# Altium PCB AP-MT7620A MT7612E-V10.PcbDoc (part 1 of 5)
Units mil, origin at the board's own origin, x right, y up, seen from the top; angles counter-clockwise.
Board outline 4645.67 x 3740.16 mil, 4 copper layers (Top, Inner Layer 2, Inner Layer 3, Bottom), stack 35.4 mil thick; 603 components, 409 nets, 1850 pads, 2004 vias.
Unrouted connection lines stored in the file: 90.
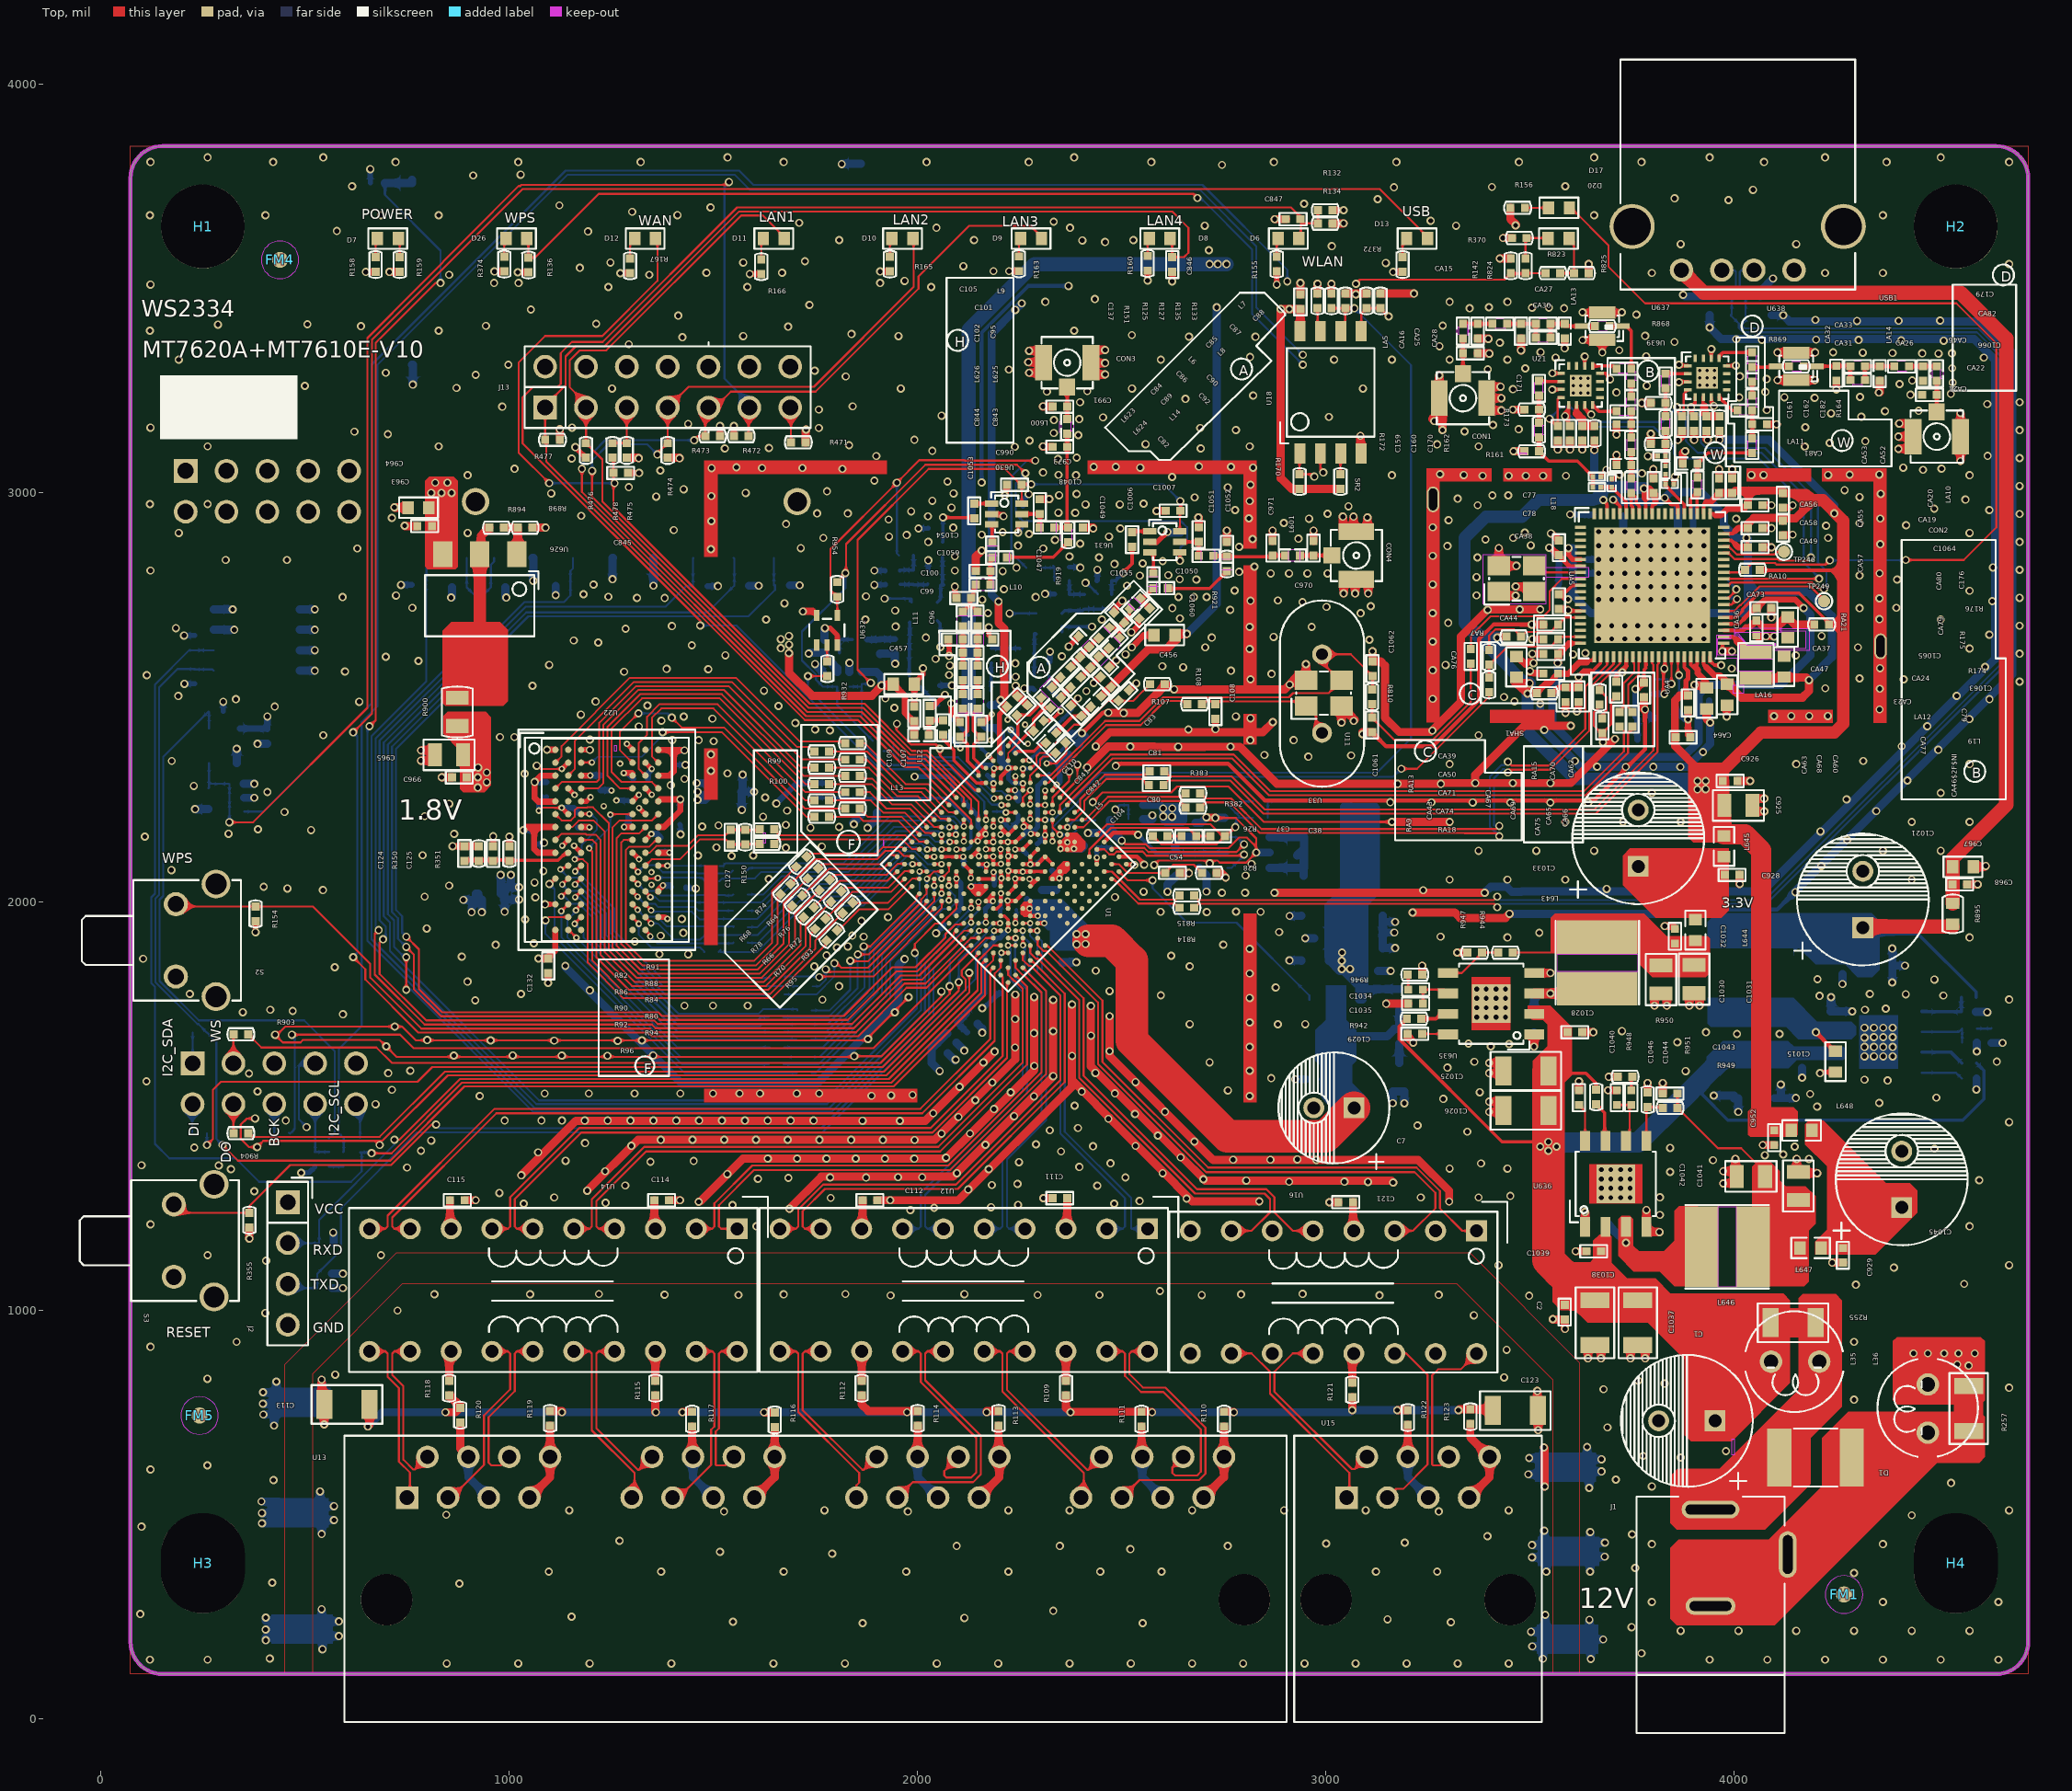
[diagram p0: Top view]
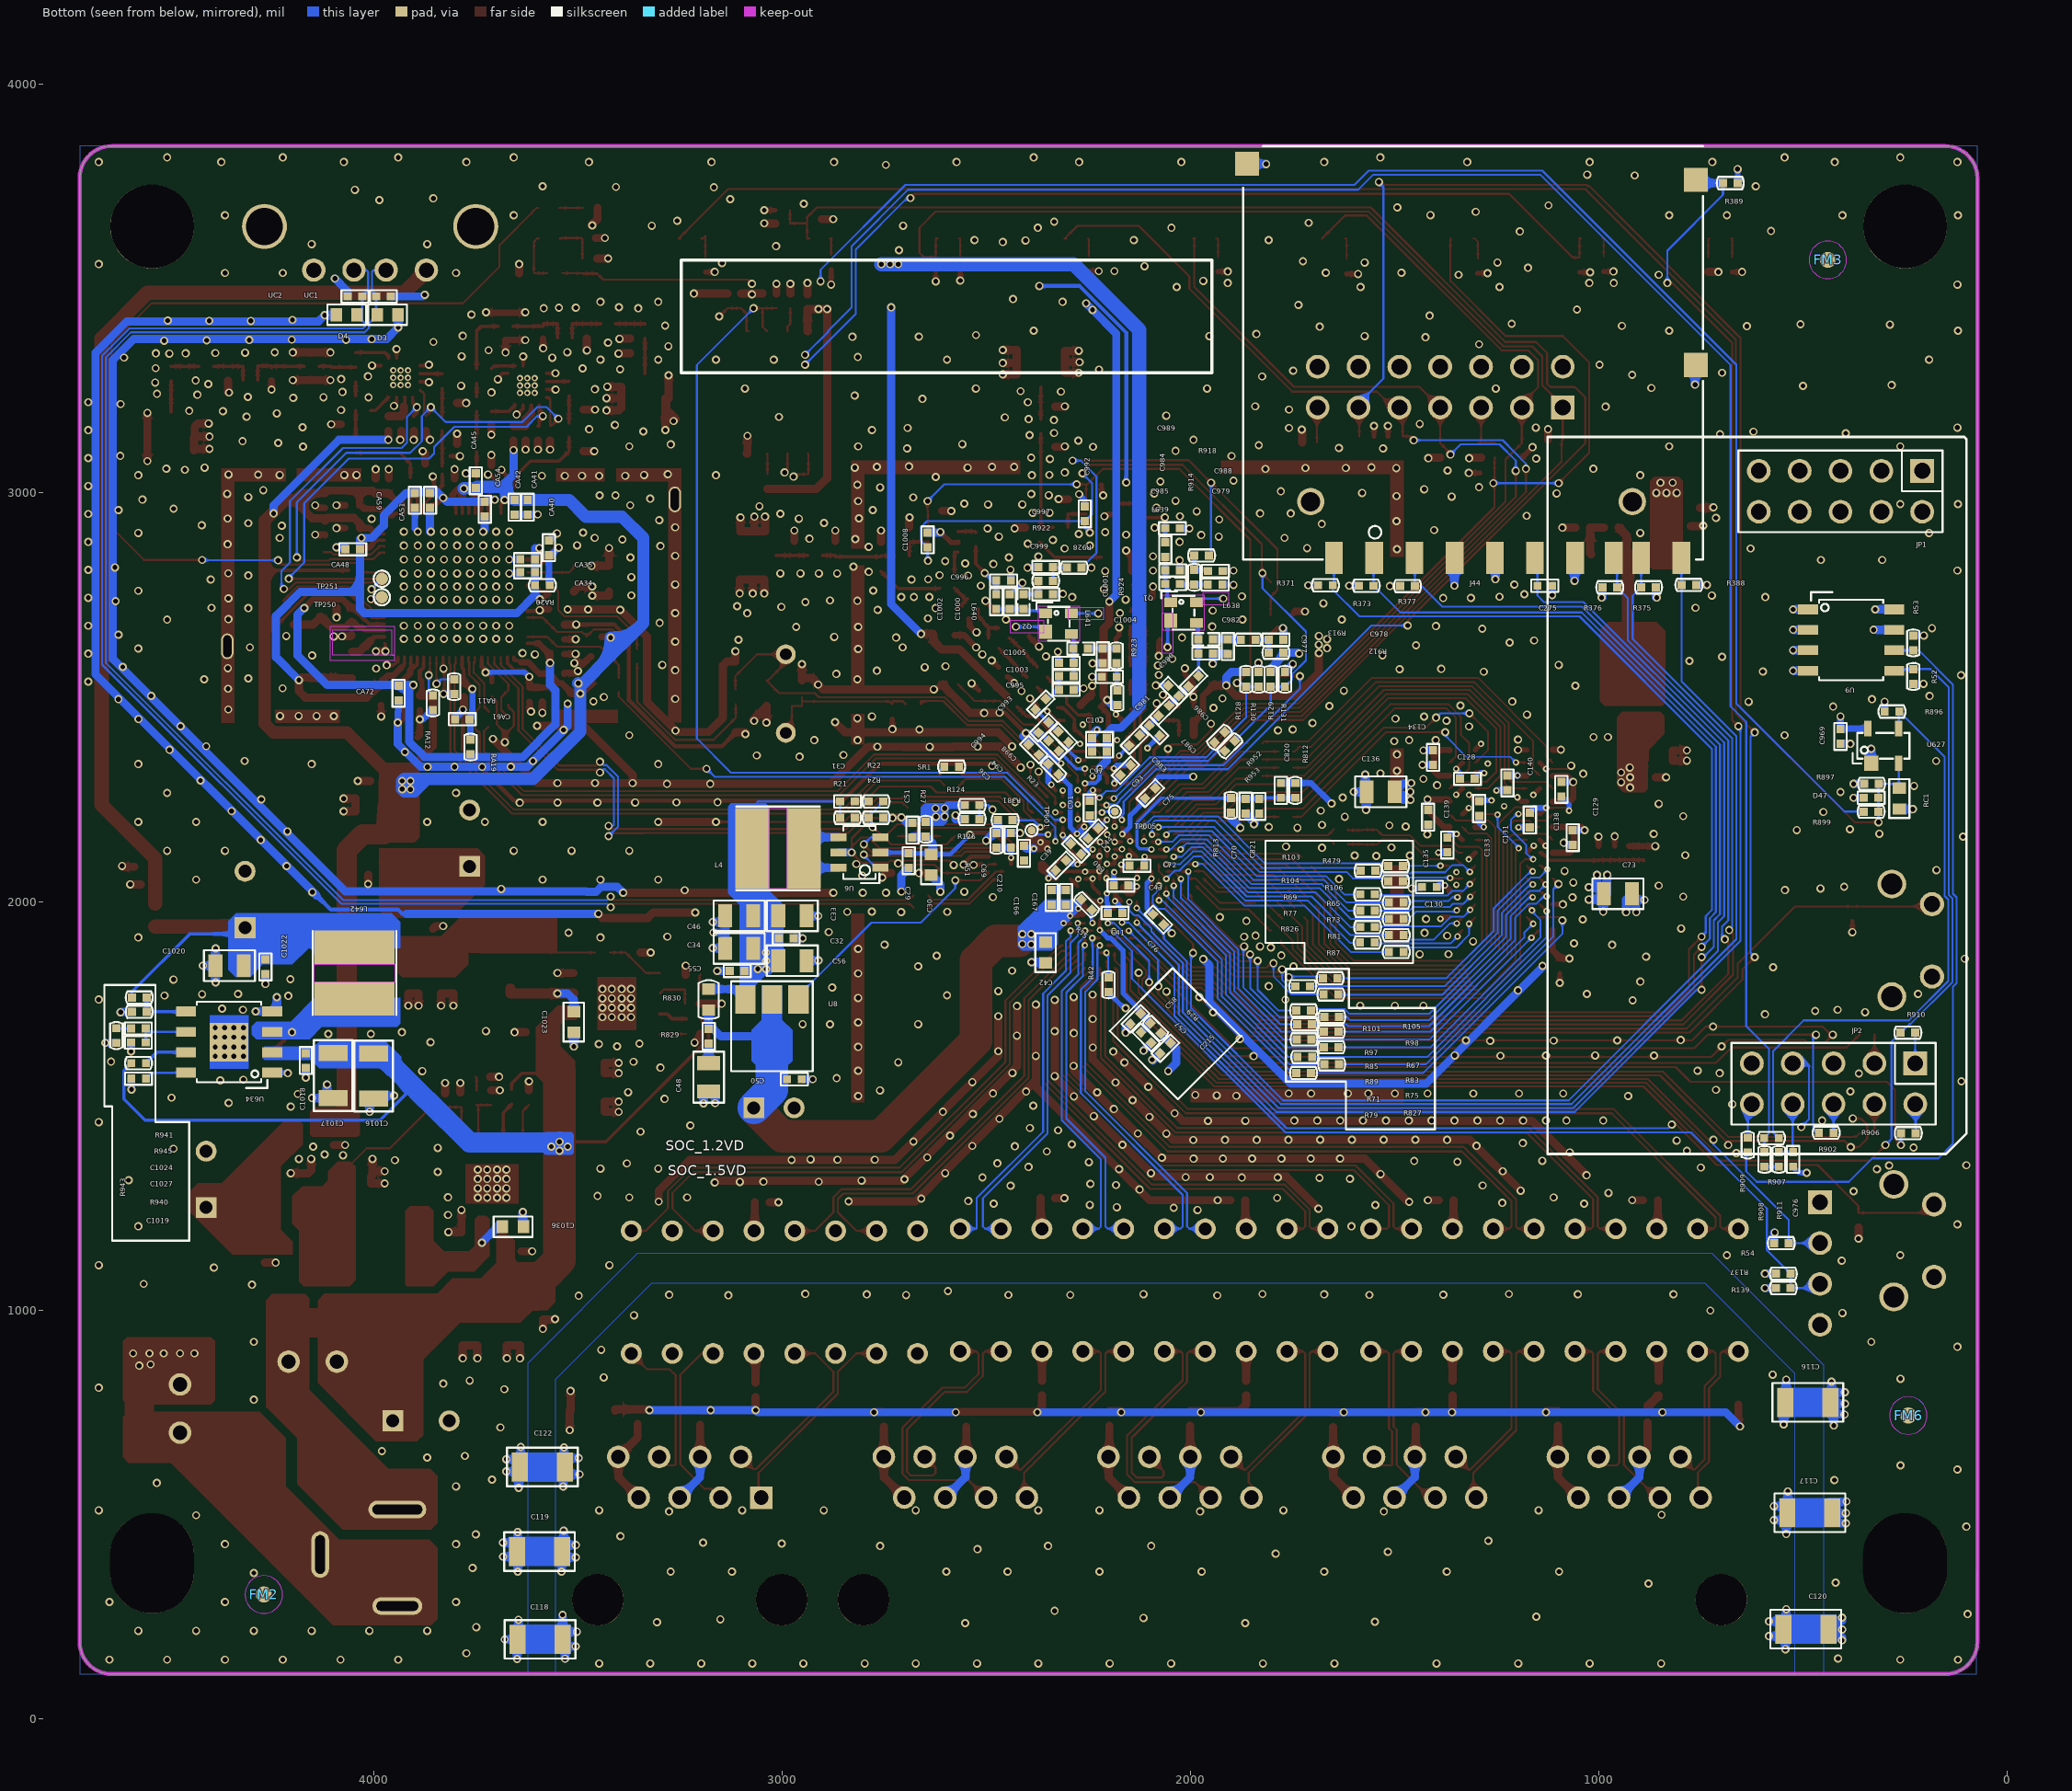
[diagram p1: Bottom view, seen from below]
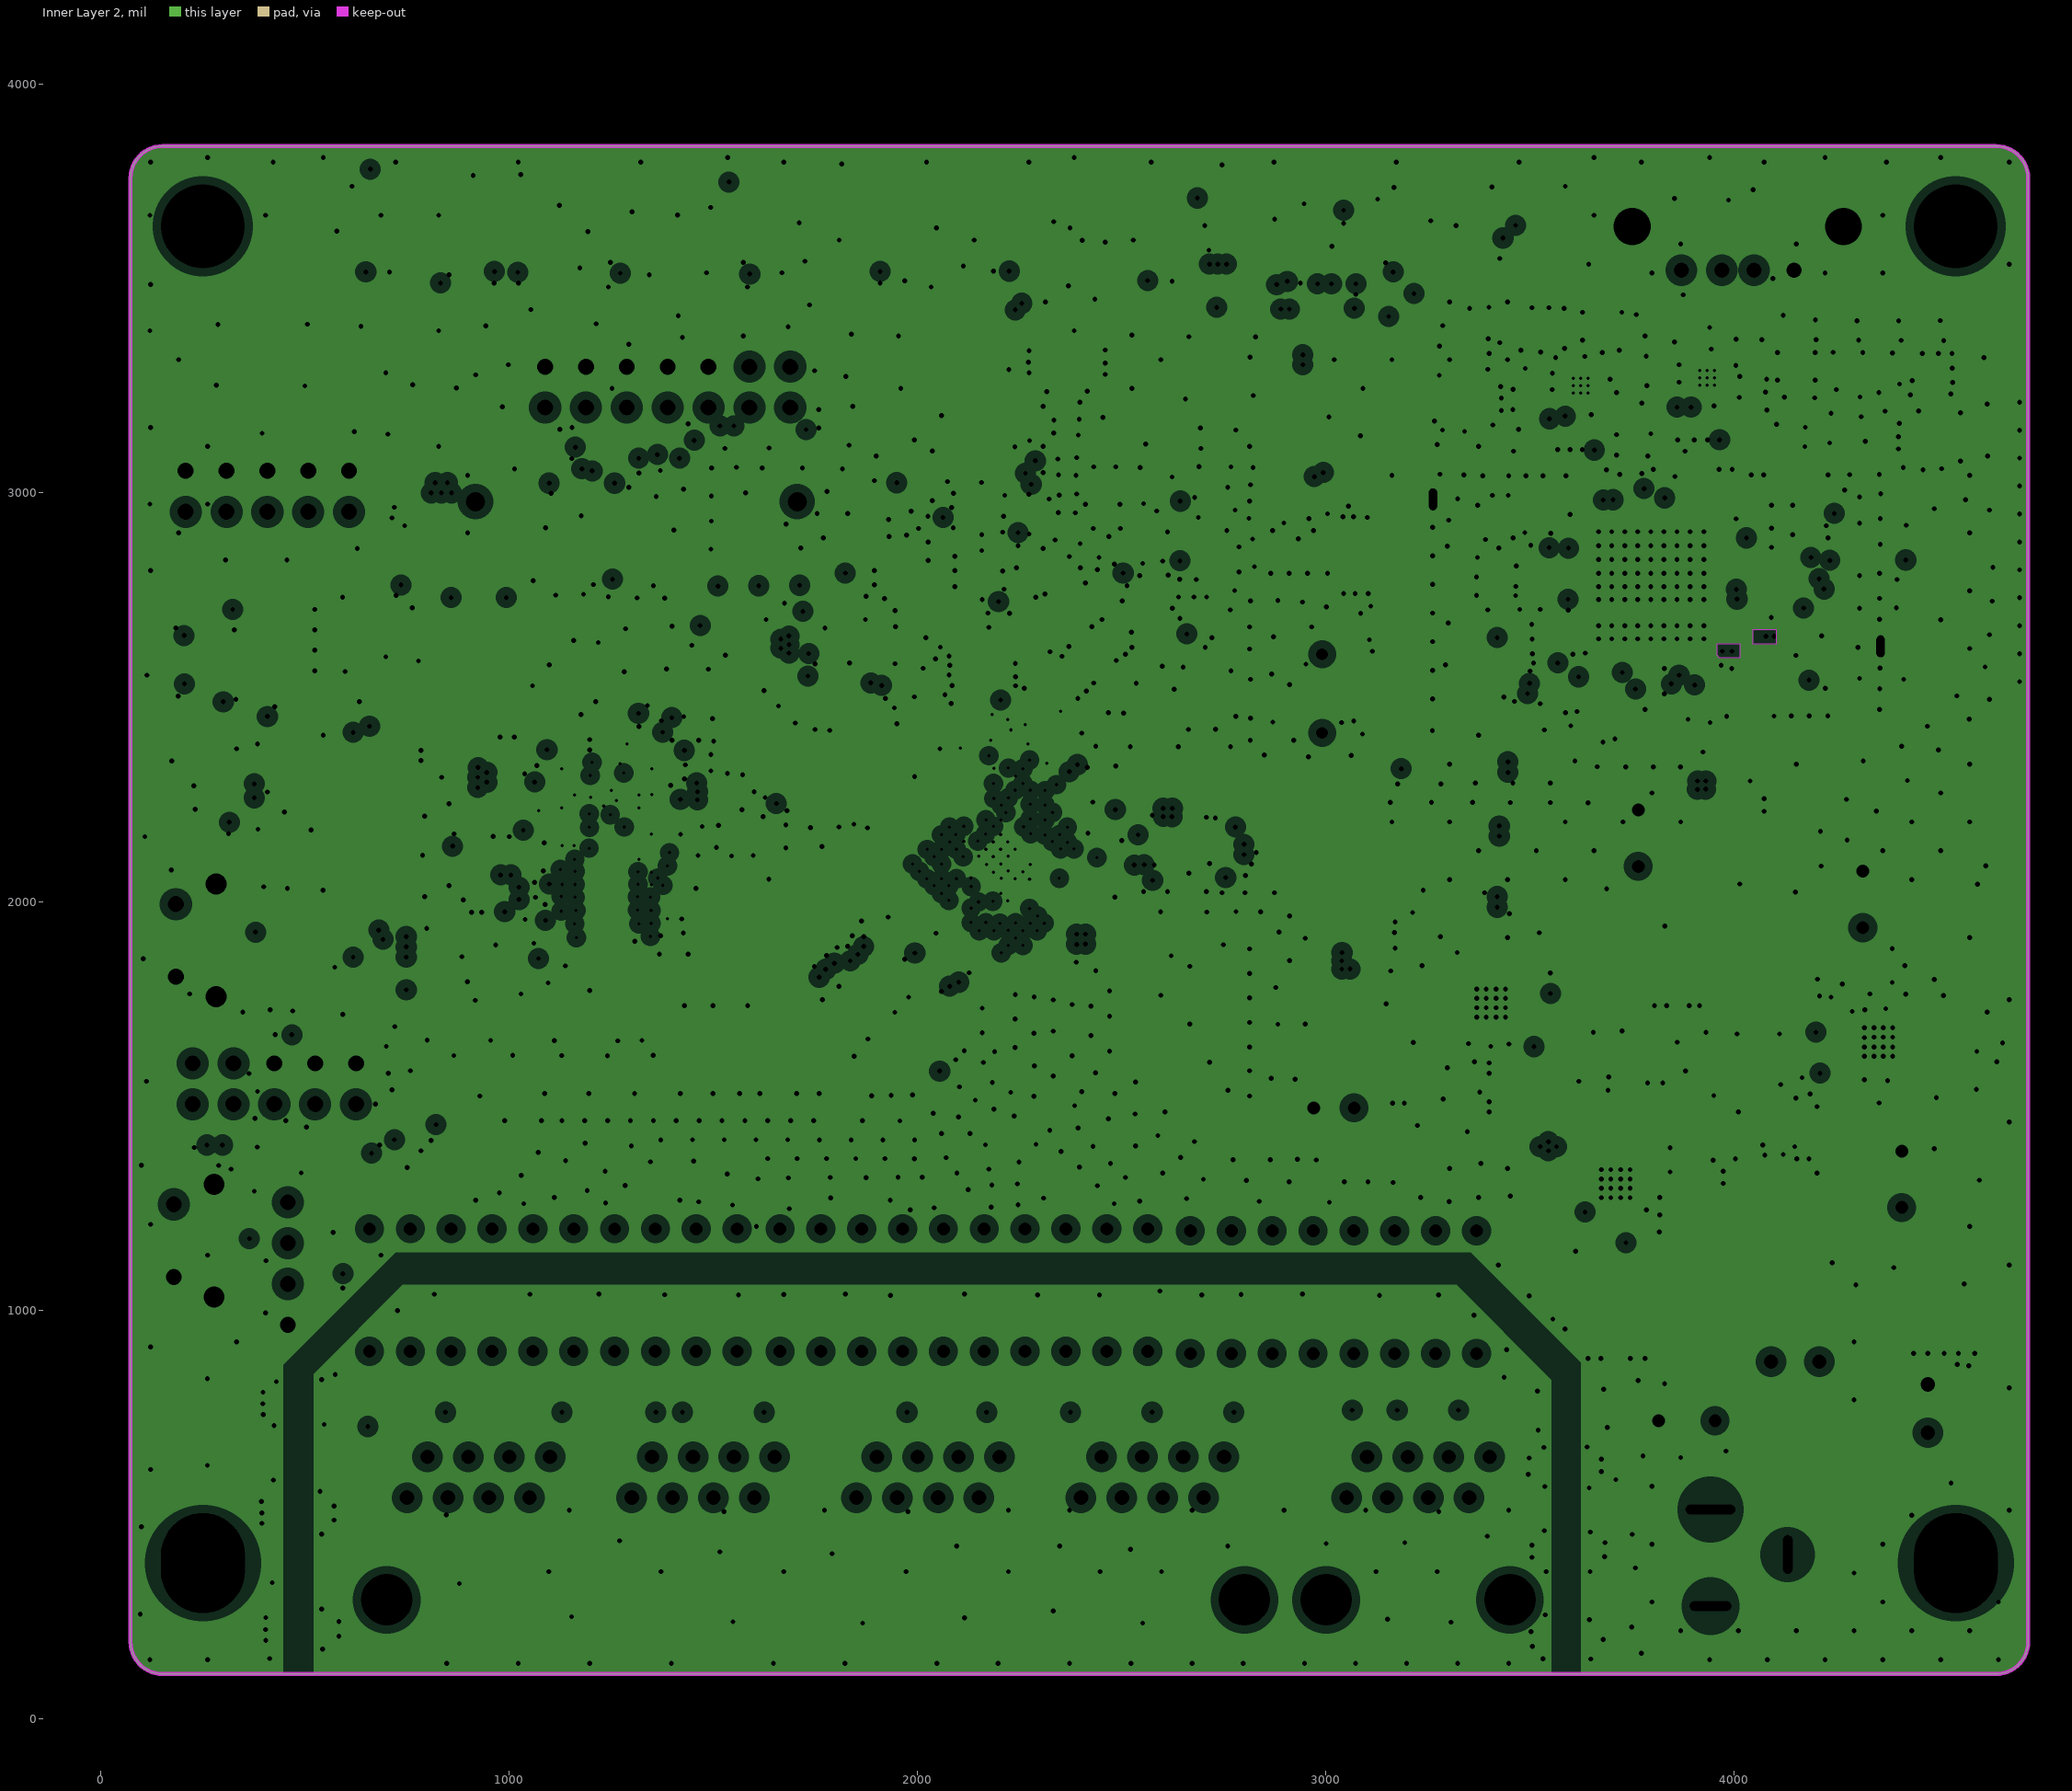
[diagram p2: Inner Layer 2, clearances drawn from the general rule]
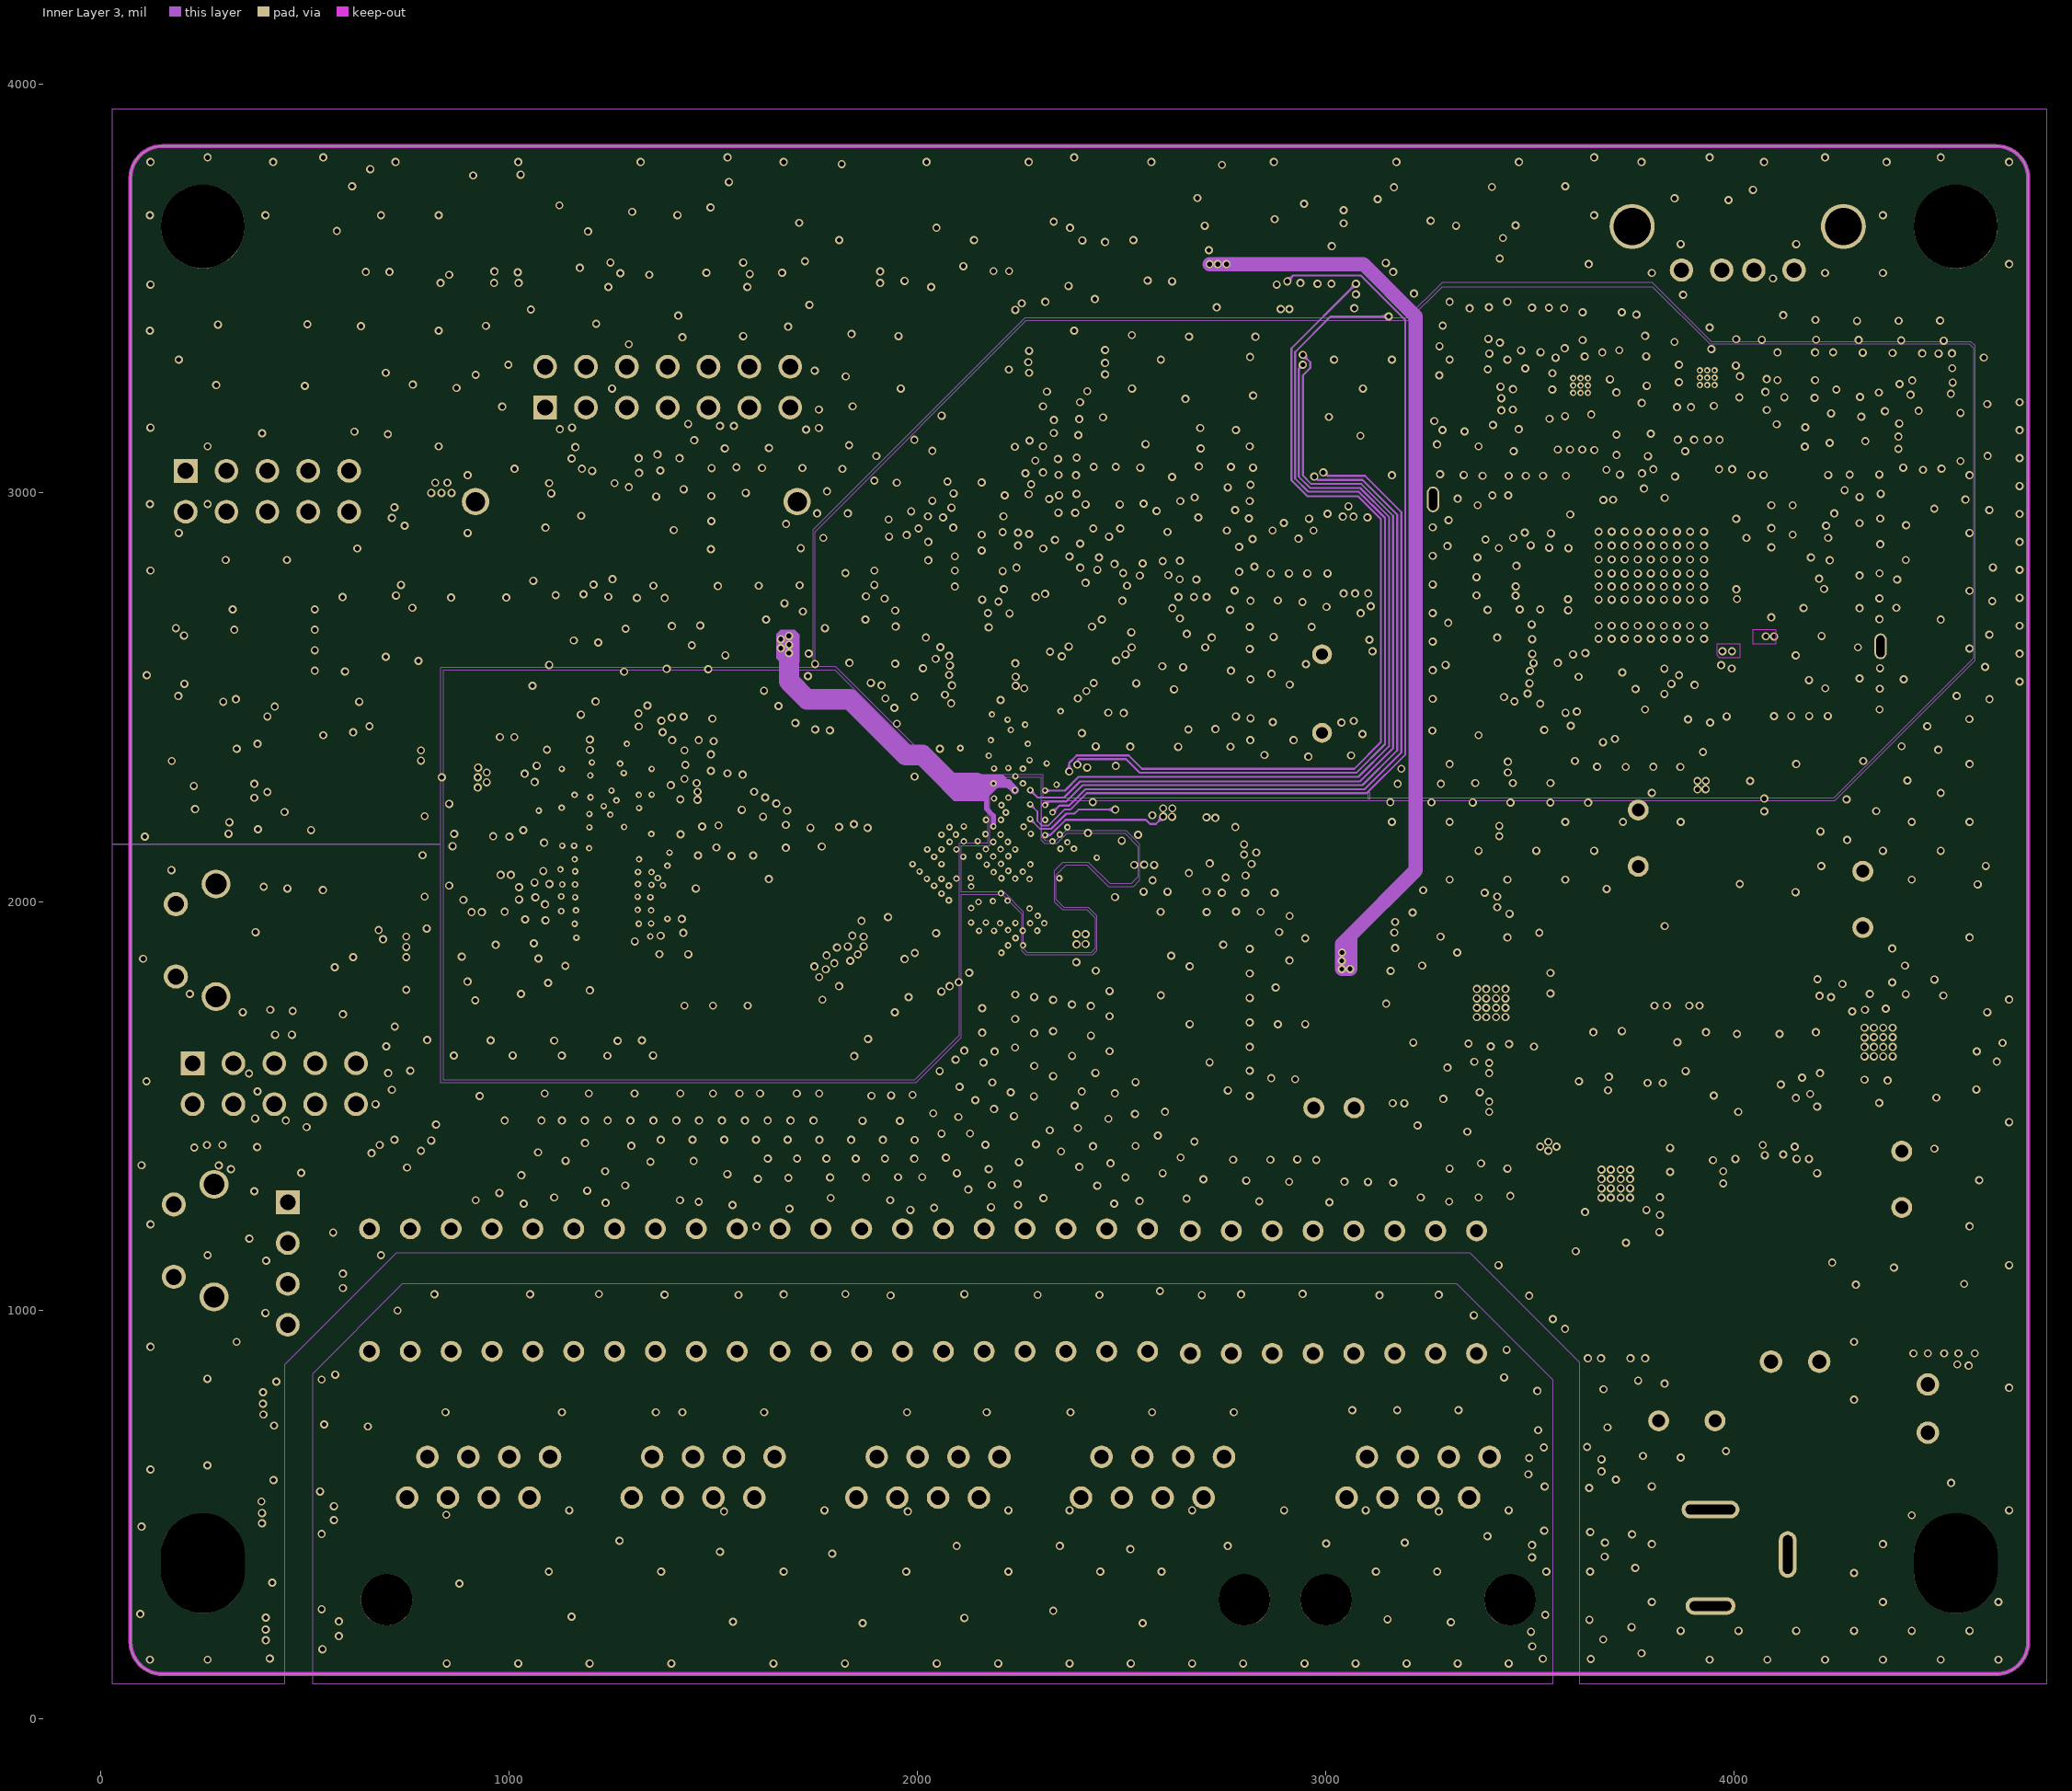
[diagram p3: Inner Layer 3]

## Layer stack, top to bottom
Solder Mask Top: solder mask 0.4, Solder Resist, Dk 3.5
Top: signal copper 1.35
Dielectric 1: dielectric 10, FR-4, Dk 4.3
Inner Layer 2: plane copper 1.35
Dielectric2: dielectric 10, FR-4, Dk 4.3
Inner Layer 3: signal copper 1.35
Dielectric3: dielectric 10, FR-4, Dk 4.3
Bottom: signal copper 1.35
Solder Mask Bottom: solder mask 0.4, Solder Resist, Dk 3.5

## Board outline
74,3770.42 74,187.74 ccw(c152.74,187.74) 152.74,109 4640.93,109 ccw(c4640.93,187.74) 4719.67,187.74 4719.67,3770.42 ccw(c4640.93,3770.42) 4640.93,3849.16 152.74,3849.16 ccw(c152.74,3770.42)

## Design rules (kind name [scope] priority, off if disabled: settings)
Clearance "Clearance - Net - GND - DDR" [InNet('GND') vs InNetClass('DDR')] p1: gap=5 ignorepadtopadclearanceinfootprint=FALSE except(0: Arc-Hole Track-Hole SMDPad-Hole THPad-Hole Via-Hole Fill-Hole Poly-Hole Region-Hole Text-Hole; 4: Arc-Arc Arc-Track Arc-SMDPad Arc-THPad Arc-Via Track-Track Track-SMDPad Track-THPad Track-Via SMDPad-THPad SMDPad-Via THPad-THPad THPad-Via Via-Via; 7: SMDPad-SMDPad; 10: Arc-Text Track-Text SMDPad-Text THPad-Text Via-Text Fill-Fill Fill-Poly Fill-Region Fill-Text Poly-Poly Poly-Region Poly-Text Region-Region Region-Text Text-Text)
Clearance "Clearance - Net - GND - PHY_ETH" [InNet('GND') vs InNetClass('PHY_ETH')] p2: gap=5 ignorepadtopadclearanceinfootprint=FALSE except(0: Arc-Hole Track-Hole SMDPad-Hole THPad-Hole Via-Hole Fill-Hole Poly-Hole Region-Hole Text-Hole; 4: Arc-Arc Arc-Track Arc-SMDPad Arc-THPad Arc-Via Track-Track Track-SMDPad Track-THPad Track-Via SMDPad-THPad SMDPad-Via THPad-THPad THPad-Via Via-Via; 7: SMDPad-SMDPad; 10: Arc-Text Track-Text SMDPad-Text THPad-Text Via-Text Fill-Fill Fill-Poly Fill-Region Fill-Text Poly-Poly Poly-Region Poly-Text Region-Region Region-Text Text-Text)
Clearance "Clearance - Net - GND - USB" [InNet('GND') vs InNetClass('USB')] p3: gap=4.5 ignorepadtopadclearanceinfootprint=FALSE except(0: Arc-Hole Track-Hole SMDPad-Hole THPad-Hole Via-Hole Fill-Hole Poly-Hole Region-Hole Text-Hole; 4: Arc-Arc Arc-Track Arc-SMDPad Arc-THPad Arc-Via Track-Track Track-SMDPad Track-THPad Track-Via SMDPad-THPad SMDPad-Via THPad-THPad THPad-Via Via-Via; 7: SMDPad-SMDPad; 10: Arc-Text Track-Text SMDPad-Text THPad-Text Via-Text Fill-Fill Fill-Poly Fill-Region Fill-Text Poly-Poly Poly-Region Poly-Text Region-Region Region-Text Text-Text)
Clearance "Clearance - Net - GND - RF-1" [InNet('GND') vs InNetClass('RF-1')] p4: gap=5 ignorepadtopadclearanceinfootprint=FALSE except(0: Arc-Hole Track-Hole SMDPad-Hole THPad-Hole Via-Hole Fill-Hole Poly-Hole Region-Hole Text-Hole; 4: Arc-Arc Arc-Track Arc-SMDPad Arc-THPad Arc-Via Track-Track Track-SMDPad Track-THPad Track-Via SMDPad-THPad SMDPad-Via THPad-THPad THPad-Via Via-Via; 10: Arc-Text Track-Text SMDPad-Text THPad-Text Via-Text Fill-Fill Fill-Poly Fill-Region Fill-Text Poly-Poly Poly-Region Poly-Text Region-Region Region-Text Text-Text)
Clearance "Clearance - Net - GND - PCIE" [InNet('GND') vs InNetClass('PCIE')] p5: gap=5 ignorepadtopadclearanceinfootprint=FALSE except(0: Arc-Hole Track-Hole SMDPad-Hole THPad-Hole Via-Hole Fill-Hole Poly-Hole Region-Hole Text-Hole; 4: Arc-Arc Arc-Track Arc-SMDPad Arc-THPad Arc-Via Track-Track Track-SMDPad Track-THPad Track-Via SMDPad-THPad SMDPad-Via THPad-THPad THPad-Via Via-Via; 7: SMDPad-SMDPad; 10: Arc-Text Track-Text SMDPad-Text THPad-Text Via-Text Fill-Fill Fill-Poly Fill-Region Fill-Text Poly-Poly Poly-Region Poly-Text Region-Region Region-Text Text-Text)
Clearance "Clearance - Net - GND - RF" [InNet('GND') vs InNetClass('RF')] p6: gap=5 ignorepadtopadclearanceinfootprint=FALSE except(0: Arc-Hole Track-Hole SMDPad-Hole THPad-Hole Via-Hole Fill-Hole Poly-Hole Region-Hole Text-Hole; 4: Arc-Arc Arc-Track Arc-SMDPad Arc-THPad Arc-Via Track-Track Track-SMDPad Track-THPad Track-Via SMDPad-THPad SMDPad-Via THPad-THPad THPad-Via Via-Via; 7: SMDPad-SMDPad; 10: Arc-Text Track-Text SMDPad-Text THPad-Text Via-Text Fill-Fill Fill-Poly Fill-Region Fill-Text Poly-Poly Poly-Region Poly-Text Region-Region Region-Text Text-Text)
Clearance "Clearance - NetClass - RF-1" [InNetClass('RF-1')] p7: gap=4 ignorepadtopadclearanceinfootprint=FALSE except(0: Arc-Hole Track-Hole SMDPad-Hole THPad-Hole Via-Hole Fill-Hole Poly-Hole Region-Hole Text-Hole; 5: Arc-Arc Arc-Track Arc-SMDPad Arc-THPad Arc-Via Track-Track Track-SMDPad Track-THPad Track-Via SMDPad-SMDPad SMDPad-THPad SMDPad-Via THPad-THPad THPad-Via Via-Via; 6: SMDPad-Fill SMDPad-Poly SMDPad-Region THPad-Fill THPad-Poly THPad-Region; 10: Fill-Fill Fill-Poly Fill-Region Poly-Poly Poly-Region Region-Region Text-Text)
Clearance "Clearance - NetClass - PHY_ETH" [InNetClass('PHY_ETH')] p8: gap=4 ignorepadtopadclearanceinfootprint=FALSE except(0: Arc-Hole Track-Hole SMDPad-Hole THPad-Hole Via-Hole Fill-Hole Poly-Hole Region-Hole Text-Hole; 5: Arc-Arc Arc-Track Arc-Via Track-Track Track-Via SMDPad-SMDPad Via-Via; 6: SMDPad-Fill SMDPad-Poly SMDPad-Region THPad-Fill THPad-Poly THPad-Region; 10: Fill-Fill Fill-Poly Fill-Region Poly-Poly Poly-Region Region-Region Text-Text)
Clearance "Clearance - Default - DEFAULT- SMD" [IsVia vs IsSMTPin] p9: gap=2 ignorepadtopadclearanceinfootprint=FALSE
Clearance "Clearance - Default - DEFAULT - Via" [IsVia vs IsVia] p10: gap=0 ignorepadtopadclearanceinfootprint=FALSE
Clearance "Clearance - Default - DEFAULT - Net" [All] p11: gap=4 ignorepadtopadclearanceinfootprint=FALSE except(0: Arc-Hole Track-Hole SMDPad-Hole THPad-Hole Via-Hole Fill-Hole Poly-Hole Region-Hole Text-Hole; 6: SMDPad-Fill SMDPad-Poly SMDPad-Region THPad-Fill THPad-Poly THPad-Region; 7: SMDPad-SMDPad; 10: Fill-Fill Fill-Poly Fill-Region Poly-Poly Poly-Region Region-Region Text-Text)
ComponentClearance "ComponentClearance - Default - DEFAULT" [All] p1: gap=0 collisioncheckmode=3 verticalgap=10 showdistances=FALSE
FanoutControl Fanout_SOIC [IsSOIC] p1: bgadir=Out bgaviamode=Centered fanoutstyle=Auto fanoutdirection=Alternating viagrid=1 // Fanout_SOIC (Default Rule)
FanoutControl Fanout_Small [(CompPinCount < 5)] p2: bgadir=Out bgaviamode=Centered fanoutstyle=Auto fanoutdirection=OutThenIn viagrid=1 // Fanout_Small (Default Rule)
FanoutControl Fanout_BGA [IsBGA] p3: bgadir=Out bgaviamode=Centered fanoutstyle=Auto fanoutdirection=Alternating viagrid=1 // Fanout_BGA (Default Rule)
FanoutControl Fanout_LCC [IsLCC] p4: bgadir=Out bgaviamode=Centered fanoutstyle=Auto fanoutdirection=Alternating viagrid=1 // Fanout_LCC (Default Rule)
HoleToHoleClearance "HoleToHoleClearance - Default - DEFAULT" [All] p1: gap=5 allowstackedmicrovias=TRUE
Length "Default Length" [All] p1: maxlimit=50000 minlimit=0
MaxMinImpedance "Default Impedance" [All] p1: minimum=50.00 maximum=150.0
ParallelSegment "Default Parallel Segment Adjasent" [All] p1: limit=1000 gap=200
ParallelSegment "Default Parallel Segment Same Layer" [All] p2: limit=1000 gap=200
PlaneClearance "PlaneClearance - FootPrint 'L$2F$IND$2F$DIP$2F$D6H14'" [HasFootprint('L$2F$IND$2F$DIP$2F$D6H14')] p1: clearance=15 // PAD - Power Plane Clearance
PlaneConnect "PlaneConnect - FootPrint 'SHIELDING$2F$MPCIE$2F$2H$2F$T2'" [HasFootprint('SHIELDING$2F$MPCIE$2F$2H$2F$T2')] p1: planeconnectstyle=Direct reliefexpansion=5 reliefentries=4 reliefconductorwidth=15 reliefairgap=0
PlaneConnect "PlaneConnect - FootPrint 'L$2F$IND$2F$DIP$2F$D6H14'" [HasFootprint('L$2F$IND$2F$DIP$2F$D6H14')] p2: planeconnectstyle=Relief reliefexpansion=10 reliefentries=4 reliefconductorwidth=25 reliefairgap=10
PlaneConnect "Default PlaneConnect" [All] p3: planeconnectstyle=Relief reliefexpansion=20 reliefentries=0 reliefconductorwidth=15 reliefairgap=10
PolygonConnect "PolygonConnect - Default SMT" [IsSMTPin] p1: connectstyle=Direct reliefconductorwidth=10 reliefentries=4 polygonreliefangle="45 Angle" airgapwidth=10
PolygonConnect "PolygonConnect - FootPrint 'L$2F$IND$2F$DIP$2F$D6H14'" [HasFootprint('L$2F$IND$2F$DIP$2F$D6H14')] p2: connectstyle=Relief reliefconductorwidth=25 reliefentries=4 polygonreliefangle="90 Angle" airgapwidth=10
PolygonConnect "PolygonConnect - FootPrint 'SHIELDING$2F$MPCIE$2F$2H$2F$T2'" [HasFootprint('SHIELDING$2F$MPCIE$2F$2H$2F$T2')] p3: connectstyle=Direct reliefconductorwidth=15 reliefentries=4 polygonreliefangle="45 Angle" airgapwidth=10
PolygonConnect "PolygonConnect - Default Pad" [All] p4: connectstyle=Relief reliefconductorwidth=15 reliefentries=4 polygonreliefangle="45 Angle" airgapwidth=10
RoutingLayers "RoutingLayers - Default - DEFAULT" [All] p1: top layer_v5=TRUE mid layer 1_v5=TRUE bottom layer_v5=TRUE
RoutingPriority "RoutingPriority - Default - DEFAULT" [All] p1: routingpriority=3
RoutingTopology "Default Routing Topology" [All] p1: topology=Shortest
RoutingVias "RoutingVias - Default - DEFAULT" [All] p1: holewidth=12 width=20 viastyle="Through Hole" minholewidth=12 minwidth=20 maxholewidth=12 maxwidth=20
SMDToCorner "SMDToCorner - Default - DEFAULT" [All] p1: distance=0
SolderMaskExpansion "SolderMaskExpansion from CAM settings" [All] p1: expansion=2
Width "Width - NetClass - RF" [InNetClass('RF') OR InNetClass('RF-1')] p1: maxlimit=200 minlimit=4 preferedwidth=8
Width "Default Width" [All] p2: maxlimit=200 minlimit=4 preferedwidth=5
18 further rules are at their usual default settings.

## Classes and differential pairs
net class MLNetGroup5: DDR_CASN DDR_CSN DDR_MODT DDR_RASN MA0 MA2 MA4 MA6 MA8 MA11 MA13 MADDR0 MADDR2 MADDR4 MADDR6 MADDR8 MADDR11 MADDR13 MCAS_N MCS_N MODT MRAS_N
net class MLNetGroup2: PA1_OUT+ PA1_OUT- PA1_OUT_1 RF1_PA_OUTN RFOUT_G1
net class USB: UPHY0_PADM UPHY0_PADM_0 UPHY0_PADP UPHY0_PADP_0
net class RF-1: N17402468 N17402470 N17624866 N17949038 N17949508 N17950058 N17950072 N17950102 N17950600 N17950647 N17950661 N17951357 N179502195 N179507645 N179512821 N179513811 RF_5G_A WF0_RF_5G_RX_AUXIN WF0_RF_5G_TR WF0_RF_5G_TR_1 WF0_RF_5G_TRX WF0_RF_5G_TRX_SW WF0_RF_5G_TX WF1_RF_5G_RX_AUXIN WF1_RF_5G_TR WF1_RF_5G_TRX WF1_RF_5G_TRX_SW WF1_RF_5G_TX X00008 X00009
net class RF: ANTENNA_0 ANTENNA_1 LNA_RX0_IN LNA_RX1_IN LNA_V0 LNAO0 LNAO1 N17231224 N17723672 N17723760 N17723789 N17732056 N17758787 N17758919 N17841324 N17849608 N17851480 N17873514 N17876104 N17877881 N17881699 N17897796 N17903155 N17924652 N21240349 O_N O_N_1 O_P O_P_1 PA0_OUT+ PA0_OUT- PA0_OUT_1 PA1_OUT+ PA1_OUT- PA1_OUT_1 RF0_2G_RX_1 RF0_2G_TR RF0_LNA_IN RF0_PA_OUTN RF0_PA_OUTP RF1_2G_RX_1 RF1_2G_TR RF1_LNA_IN RF1_PA2 RF1_PA_OUTN RF1_PA_OUTP RFOUT_G0 RFOUT_G1
net class PHY_ETH: RXIM0 RXIM1 RXIM2 RXIM3 RXIM4 RXIP0 RXIP1 RXIP2 RXIP3 RXIP4 TXOM0 TXOM1 TXOM2 TXOM3 TXOM4 TXOP0 TXOP1 TXOP2 TXOP3 TXOP4
net class PCIE: APCK_RFCKO_N APCK_RFCKO_P APCK_RFCKON APCK_RFCKOP N20386056 N20386057 PCIE_RXN PCIE_RXP PCIE_TX_N PCIE_TX_P PCIE_TXN PCIE_TXP
net class DDR: CLK_N CLK_P DDR_BA0 DDR_BA1 DDR_BA2 DDR_CLK_N DDR_CLK_P DDR_MCKE DDR_MDQM0 DDR_MDQM1 DDR_MDQS0 DDR_MDQS1 DDR_WEN MA1 MA3 MA5 MA7 MA9 MA10 MA12 MADDR1 MADDR3 MADDR5 MADDR7 MADDR9 MADDR10 MADDR12 MBA0 MBA1 MBA2 MCKE MD0 MD1 MD2 MD3 MD4 MD5 MD6 MD7 MD8 MD9 MD10 MD11 MD12 MD13 MD14 MD15 MDATA0 MDATA1 MDATA2 MDATA3 MDATA4 MDATA5 MDATA6 MDATA7 MDATA8 MDATA9 MDATA10 MDATA11 MDATA12 MDATA13 MDATA14 MDATA15 MDQM0 MDQM1 MDQS0 MDQS1 MWE_N

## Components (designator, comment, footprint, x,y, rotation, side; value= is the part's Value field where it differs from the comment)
C1 "C680UF6.3V$2F$D8H11" C680UF6.3V$2F$D8H11 3884,729 r180 top
C2 "C0402" C0402 3585,995 r270 top
C7 "C100UF25V$2F$D6.3H11.5" C100UF25V$2F$D6.3H11.5 3020,1495 r180 top
C29 "C0402" C0402 2690,2100 r270 bottom
C30 "C0603" C0603 2635,2090 r270 bottom
C31 "C0402" C0402 2840,2245 r180 bottom
C32 "C0402" C0402 2990,1910 r180 bottom
C33 "C0805" C0805 2975,1965 r180 bottom
C34 "C0805" C0805 3105,1885 r0 bottom
C36 "C0402" C0402 2384,2372 r45 bottom
C37 "C0402" C0402 2665,2160 r180 top
C38 "C0402" C0402 2735,2160 r0 top
C39 "C0402" C0402 2317.5,2088.5 r135 bottom
C40 "C0402" C0402 2281,2128.5 r224.47 bottom
C41 "C0402" C0402 2185,1972 r0 bottom
C42 "C0603" C0603 2355,1875 r270 bottom
C43 "C0402" C0402 2170.5,2039.5 r0 bottom
C44 "C0402" C0402 2238.5,2167 r135 bottom
C46 "C0805" C0805 3105,1965 r0 bottom
C48 "C0805" C0805 3180,1570 r270 bottom
C50 "C0402" C0402 2970,1565 r180 bottom
C51 "C0402" C0402 2681,2175 r90 bottom
C54 "C0402" C0402 2625,2070 r0 top
C55 "C0402" C0402 3110,1830 r0 bottom
C56 "C0805" C0805 2975,1855 r180 bottom
C57 "C0402" C0402 2109,1667 r225 bottom
C58 "C0402" C0402 2135,1713 r315 bottom
C69 "C0402" C0402 2440,2150 r270 bottom
C70 "C0402" C0402 1865.5,2233.5 r270 bottom
C72 "C0402" C0402 2131.5,2087.5 r0 bottom
C73 "C0805" C0805 954,2019 r180 bottom
C75 "C0402" C0402 2099,2265 r135 bottom
C76 "C0402" C0402 2079,1956 r225 bottom
C77 "C0201" C0201 3664,3040 r0 top
C78 "C0201" C0201 3664,3014 r0 top
C79 "C0201" C0201 3832,3056 r270 top
C80 "C0402" C0402 2585,2285 r0 top
C81 "C0402" C0402 2586.5,2318.5 r0 top
C82 "C0402" C0402 2388.5,2466.5 r315 top
C83 "C0402" C0402 2505.5,2504.5 r45 top
C84 "C0402" C0402 2363.19,2561.47 r45 top
C85 "C0402" C0402 2457.5,2657.21 r45 top
C86 "C0402" C0402 2411.5,2585.5 r135 top
C87 "C0402" C0402 2494,2695 r135 top
C88 "C0402" C0402 2556.5,2705 r225 top
C89 "C0402" C0402 2387.94,2536.72 r45 top
C90 "C0402" C0402 2457.5,2586.5 r315 top
C91 "C0402" C0402 2247,2229 r270 bottom
C92 "C0402" C0402 2461.5,2537.5 r315 top
C93 "C0402" C0402 2159.5,2321.5 r135 bottom
C94 "C0402" C0402 2335,2381 r45 bottom
C95 "C0402" C0402 2147.5,2559.5 r90 top
C96 "C0402" C0402 2147.5,2691.5 r90 top
C97 "C0402" C0402 2223,2367.5 r0 bottom
C99 "C0402" C0402 2114,2743 r180 top
C100 "C0402" C0402 2161,2809 r180 top
C101 "C0402" C0402 2129.5,2609.5 r0 top
C102 "C0402" C0402 2111.5,2559.5 r90 top
C103 "C0402" C0402 2223,2400 r0 bottom
C104 "C0402" C0402 2351,2376 r45 top
C105 "C0402" C0402 2093.5,2641.5 r180 top
C107 "C0402" C0402 2030.5,2460.5 r270 top
C108 "C0402" C0402 2730,2465 r270 top
C109 "C0402" C0402 1992.5,2459.5 r270 top
C110 "C0402" C0402 2232.5,2489.5 r45 top
C111 "C0402" C0402 2349,1274 r180 top
C112 "C0402" C0402 1884,1269 r0 top
C113 "C1206" C1206 604,769 r180 top
C114 "C0402" C0402 1374,1269 r0 top
C115 "C0402" C0402 874,1269 r0 top
C116 "SB$2F$1206" SB$2F$1206 489,774 r0 bottom
C117 "SB$2F$1206" SB$2F$1206 484,504 r0 bottom
C118 "SB$2F$1206" SB$2F$1206 3592.48,194.11 r180 bottom
C119 "SB$2F$1206" SB$2F$1206 3594,409 r180 bottom
C120 "SB$2F$1206" SB$2F$1206 494,219 r0 bottom
C121 "C0402" C0402 3049,1264 r180 top
C122 "SB$2F$1206" SB$2F$1206 3587,616 r180 bottom
C123 "C1206" C1206 3464,754 r0 top
C124 "C0402" C0402 891.5,2117.5 r270 top
C125 "C0402" C0402 961.5,2117.5 r90 top
C127 "C0402" C0402 1543.5,2157.5 r270 top
C128 "C0402" C0402 1322.5,2300.5 r0 bottom
C129 "C0402" C0402 1064.5,2156.5 r270 bottom
C130 "C0402" C0402 1415.5,2035.5 r0 bottom
C131 "C0402" C0402 1169.5,2199.5 r90 bottom
C132 "C0402" C0402 1096.5,1842.5 r270 top
C133 "C0402" C0402 1293.5,2227.5 r90 bottom
C134 "C0402" C0402 1406.5,2352.5 r270 bottom
C135 "C0402" C0402 1418.5,2206.5 r270 bottom
C136 "C0805" C0805 1534.5,2268.5 r0 bottom
C137 "C0402" C0402 2938,3468 r90 top
C138 "C0402" C0402 1092.5,2274.5 r270 bottom
C139 "C0402" C0402 1371.5,2138.5 r90 bottom
C140 "C0402" C0402 1224.5,2290.5 r270 bottom
C159 "C0402" C0402 3568,3146 r90 top
C160 "C0402" C0402 3598,3146 r90 top
C161 "C0402" C0402 3872,3170 r90 top
C162 "C0402" C0402 3902,3170 r90 top
C166 "C0402" C0402 2340,2010 r90 bottom
C167 "C0402" C0402 2305,2010 r90 bottom
C170 "C0402" C0402 3628,3146 r90 top
C171 "C0402" C0402 3522,3256 r90 top
C176 "C0402" C0402 3832,3274 r90 top
C179 "C0402" C0402 4044,3326 r270 top
C182 "C0402" C0402 3932,3170 r90 top
C210 "C0402" C0402 2408,2118 r270 bottom
C215 "C0402" C0402 2062,1641 r315 bottom
C275 "C0402" C0402 1133,2773 r180 bottom
C456 "C0603" C0603 2605.5,2652 r180 top
C457 "C0603" C0603 1967,2532 r0 top
C820 "C0402" C0402 1779,2272 r270 bottom
C821 "C0402" C0402 1832,2233 r270 bottom
C841 "C0402" C0402 2257,2468 r45 top
C842 "C0402" C0402 2297.11,2429.78 r45.51 top
C843 "C0402" C0402 2156.5,2421.5 r90 top
C844 "C0402" C0402 2104.5,2421.5 r90 top
C845 "C0402" C0402 1274,3049 r0 top
C846 "C0402" C0402 2624,3559 r270 top
C847 "C0402" C0402 2920,3670 r180 top
C925 "C0805" C0805 4010,2235 r0 top
C926 "C0402" C0402 3990,2295 r0 top
C928 "C0402" C0402 3995,2065 r0 top
C929 "C0402" C0402 4266,1134 r270 top
C952 "C0402" C0402 4098,1422 r270 top
C963 "C0402" C0402 794,2919 r180 top
C964 "C0603" C0603 779,2964 r180 top
C965 "C0805" C0805 854,2359 r180 top
C966 "C0402" C0402 879,2304 r180 top
C967 "C0603" C0603 4560,2085 r0 top
C968 "C0402" C0402 4552,2042 r0 top
C969 "C0402" C0402 409,2404 r270 bottom
C970 "C0402" C0402 2970,2865 r90 top
C971 "C0402" C0402 2870,2865 r90 top
C973 "C0402" C0402 2349,3113 r180 top
C976 "C0402" C0402 525,1369 r270 bottom
C977 "C0402" C0402 1909,2624 r90 bottom
C978 "C0402" C0402 1791,2641 r0 bottom
C979 "C0402" C0402 1940,2776 r0 bottom
C980 "C0402" C0402 1993,2539.5 r135 bottom
C981 "C0402" C0402 2065.5,2467 r135 bottom
C982 "C0402" C0402 1963,2607 r0 bottom
C983 "C0402" C0402 2137.5,2394.5 r135 bottom
C984 "C0402" C0402 2062,2861.5 r270 bottom
C985 "C0402" C0402 2044,2810.5 r180 bottom
C986 "C0402" C0402 2042,2516 r45 bottom
C987 "C0402" C0402 2088.5,2418.5 r225 bottom
C988 "C0402" C0402 1939.5,2809 r180 bottom
C989 "C0402" C0402 2044.5,2913.5 r180 bottom
C990 "C0402" C0402 2238,3020 r180 top
C991 "C0402" C0402 2349,3211 r180 top
C992 "C0402" C0402 2259,2949 r90 bottom
C993 "C0402" C0402 2367,2483 r135 bottom
C994 "C0402" C0402 2360,2426 r315 bottom
C995 "C0402" C0402 2304.5,2518 r180 bottom
C996 "C0402" C0402 2458,2785.5 r180 bottom
C997 "C0402" C0402 2354.5,2818.5 r0 bottom
C998 "C0402" C0402 2311.5,2403 r45 bottom
C999 "C0402" C0402 2354.5,2752 r0 bottom
C1000 "C0402" C0402 2442.5,2734 r90 bottom
C1001 "C0402" C0402 2215,2601.5 r90 bottom
C1002 "C0402" C0402 2476,2734 r270 bottom
C1003 "C0402" C0402 2304.5,2551.5 r180 bottom
C1004 "C0402" C0402 2199,2550 r180 bottom
C1005 "C0402" C0402 2304.5,2584 r180 bottom
C1006 "C0402" C0402 2526,2886 r270 top
C1007 "C0402" C0402 2626.5,2956.5 r180 top
C1008 "C0402" C0402 2644,2885 r90 bottom
C1015 "C0603" C0603 4248,1608 r90 top
C1016 "C1206" C1206 4000,1573 r270 bottom
C1017 "C1206" C1206 4099,1574 r270 bottom
C1018 "C0402" C0402 4166,1611 r90 bottom
C1019 "C0402" C0402 4575.5,1566.5 r180 bottom
C1020 "C0805" C0805 4353,1843 r0 bottom
C1021 "C680UF6.3V$2F$D8H11" C680UF6.3V$2F$D8H11 4315,2005 r90 top
C1022 "C0402" C0402 4265,1840 r270 bottom
C1023 "C0603" C0603 3510,1705 r90 bottom
C1024 "C0402" C0402 4576,1689 r0 bottom
C1025 "C1206" C1206 3490,1585 r180 top
C1026 "C1206" C1206 3490,1489 r180 top
C1027 "C0402" C0402 4576,1655 r180 bottom
C1028 "C0402" C0402 3610,1680 r180 top
C1029 "C0402" C0402 3218,1676 r0 top
C1030 "C0805" C0805 3821,1809 r270 top
C1031 "C0805" C0805 3902,1810 r270 top
C1032 "C0402" C0402 3855,1915 r90 top
C1033 "C680UF6.3V$2F$D8H11" C680UF6.3V$2F$D8H11 3765,2155 r90 top
C1034 "C0402" C0402 3220,1784.5 r180 top
C1035 "C0402" C0402 3220,1750 r0 top
C1036 "C0603" C0603 3659,1204 r0 bottom
C1037 "C1206" C1206 3764,969 r270 top
C1038 "C1206" C1206 3659,969 r270 top
C1039 "C0402" C0402 3656,1144 r0 top
C1040 "C0402" C0402 3620,1520 r270 top
C1041 "C0805" C0805 4157,1304 r90 top
C1042 "C0805" C0805 4041,1327 r180 top
C1043 "C0402" C0402 3843,1530 r180 top
C1044 "C0402" C0402 3748,1520 r90 top
C1045 "C680UF6.3V$2F$D8H11" C680UF6.3V$2F$D8H11 4410,1320 r90 top
C1046 "C0402" C0402 3713,1520 r270 top
C1047 "C0402" C0402 2318,2915.5 r180 top
C1048 "C0402" C0402 2300,2966.5 r90 top
C1049 "C0402" C0402 2387.48,2915.62 r0 top
C1050 "C0402" C0402 2707,2846 r180 top
C1051 "C0402" C0402 2689,2898 r90 top
C1052 "C0402" C0402 2758,2862 r90 top
C1053 "C0402" C0402 2139.5,2956 r90 top
C1054 "C0402" C0402 2183.5,2860.5 r270 top
C1055 "C0402" C0402 2578,2785 r270 top
C1059 "C0402" C0402 2201.5,2842.5 r0 top
C1060 "C0402" C0402 2596,2767 r0 top
C1061 "C0402" C0402 3113.5,2432 r90 top
C1062 "C0402" C0402 3114.5,2570 r270 top
C1063 "C0201" C0201 3822,3090 r180 top
C1064 "C0402" C0402 3730,3304 r0 top
C1065 "C0402" C0402 3730,3200 r180 top
C1066 "C0402" C0402 4026,3202 r180 top
CA15 "C0402A" C0402A 3354,3342 r0 top
CA16 "C0402A" C0402A 3372,3396 r270 top
CA19 "C0402A" C0402A 4478,3240 r180 top
CA20 "C0402A" C0402A 4462,3292 r270 top
CA21 "C0402A" C0402A 4044,3116 r270 top
CA22 "C0402A" C0402A 4062,3168 r0 top
CA23 "C0402A" C0402A 3748,3118 r270 top
CA24 "C0402A" C0402A 3730,3168 r180 top
CA25 "C0402A" C0402A 3426,3414 r180 top
CA26 "C0402A" C0402A 4410,3310 r0 top
CA27 "C0402A" C0402A 3532,3414 r0 top
CA28 "C0402A" C0402A 3478,3396 r270 top
CA30 "C0402A" C0402A 3532,3380 r0 top
CA31 "C0402A" C0402A 4302,3310 r0 top
CA32 "C0402A" C0402A 4250,3293 r270 top
CA33 "C0402A" C0402A 4302,3276 r0 top
CA34 "C0402A" C0402A 3623,2806 r0 bottom
CA35 "C0402A" C0402A 3623,2838 r0 bottom
CA36 "C0402A" C0402A 4054.14,2669.56 r270 top
CA37 "C0603" C0603 4131.16,2671.14 r270 top
CA38 "C0402A" C0402A 3571,2866 r90 top
CA39 "C0402A" C0402A 3551,2678 r180 top
CA40 "C0402A" C0402A 3571,2866 r90 bottom
CA41 "C0402A" C0402A 3623,2965 r270 bottom
CA42 "C0402A" C0402A 3655,2965 r270 bottom
CA43 "C0603" C0603 3467,2574 r90 top
CA44 "C0402A" C0402A 3571,2734 r270 top
CA45 "C0402A" C0402A 3750,3030 r90 bottom
CA46 "C0402A" C0402A 4044,3220 r90 top
CA46$2F$NI "C0402A" C0402A 3803,3018 r90 top
CA47 "C0603" C0603 4122,2575 r90 top
CA48 "C0402A" C0402A 4051,2862 r0 bottom
CA49 "C0402A" C0402A 4051,2867 r0 top
CA50 "C0402A" C0402A 3551,2642 r180 top
CA51 "C0402A" C0402A 3862,2982 r270 bottom
CA52 "C0402A" C0402A 3995,3018 r90 top
CA53 "C0402A" C0402A 3963,3018 r90 top
CA54 "C0402A" C0402A 3728,2960 r270 bottom
CA55 "C0402A" C0402A 4119,2982 r270 top
CA56 "C0402A" C0402A 4051,2970 r0 top
CA57 "C0402A" C0402A 4119,2914 r270 top
CA58 "C0402A" C0402A 4051,2914 r0 top
CA59 "C0402A" C0402A 3899,2982 r270 bottom
CA60 "C0603" C0603 3983,2506 r270 top
CA61 "C0402A" C0402A 3783,2446 r0 bottom
CA62 "C0402A" C0402A 3779.26,2517.93 r270 top
CA63 "C0402A" C0402A 3887,2486 r270 top
CA64 "C0402A" C0402A 3875,2402 r0 top
CA65 "C0402A" C0402A 3719,2446 r90 top
CA66 "C0402A" C0402A 3751,2446 r90 top
CA67 "C0402A" C0402A 3587,2506 r270 top
CA68 "C0603" C0603 3932.54,2497.22 r270 top
CA69 "C0402A" C0402A 3619,2506 r270 top
CA70 "C0402A" C0402A 3711,2520 r270 top
CA71 "C0402A" C0402A 3551,2606 r180 top
CA72 "C0402A" C0402A 3939,2510 r270 bottom
CA73 "C0402A" C0402A 4072.68,2717.93 r0 top
CA74 "C0402A" C0402A 3551,2558 r180 top
CA75 "C0402A" C0402A 3677,2430 r90 top
CA76 "C0402A" C0402A 3355,2600 r270 top
CA77 "C0402" C0402 3748,3018 r270 top
CA79 "C0402" C0402 3748,3218 r90 top
CA80 "C0402" C0402 3748,3286 r90 top
CA81 "C0402" C0402 3910,3020 r90 top
CA82 "C0402" C0402 4044,3290 r90 top
CON1 "COAXIAL$2F$SMD$2F$CON$2F$V$2F$I-PEX" COAXIAL$2F$SMD$2F$CON$2F$V$2F$I-PEX 3336,3232 r180 top
CON2 "COAXIAL$2F$SMD$2F$CON$2F$V$2F$I-PEX" COAXIAL$2F$SMD$2F$CON$2F$V$2F$I-PEX 4496,3138 r180 top
CON3 "COAXIAL$2F$SMD$2F$CON$2F$V$2F$I-PEX$2F$W08-5801" COAXIAL$2F$SMD$2F$CON$2F$V$2F$I-PEX$2F$W08-5801 2367,3319 r0 top
CON4 "COAXIAL$2F$SMD$2F$CON$2F$V$2F$I-PEX$2F$W08-5801" COAXIAL$2F$SMD$2F$CON$2F$V$2F$I-PEX$2F$W08-5801 3075,2847 r270 top
D1 "VARISTOR$2F$SMD$2F$TVM5B150L103RY" VARISTOR$2F$SMD$2F$TVM5B150L103RY 4199,639 r180 top
D3 "C0603" C0603 3966,3436 r0 bottom
D4 "C0603" C0603 4066,3436 r180 bottom
D6 "C0603" C0603 2908.65,3622.78 r0 top
D7 "C0603" C0603 703.92,3622.78 r0 top
D8 "C0603" C0603 2593.69,3622.78 r0 top
D9 "C0603" C0603 2278.72,3622.78 r0 top
D10 "C0603" C0603 1963.76,3622.78 r0 top
D11 "C0603" C0603 1648.8,3622.78 r0 top
D12 "C0603" C0603 1333.84,3622.78 r0 top
D13 "C0603" C0603 3223.61,3622.78 r0 top
D17 "C0603" C0603 3571,3698 r0 top
D20 "C0603" C0603 3570,3622.78 r0 top
D26 "C0603" C0603 1018.88,3622.78 r0 top
D47 "C0402" C0402 334,2254 r0 bottom
FM1 "FD" FD 4269,304 r0 top
FM2 "FD" FD 4269,304 r180 bottom
FM3 "FD" FD 440,3570.5 r180 bottom
FM4 "FD" FD 440,3570.5 r0 top
FM5 "FD" FD 243,742 r0 top
FM6 "FD" FD 243,742 r180 bottom
H1 "DR52" DR52 251.17,3652.31 r0 top
H2 "DR52" DR52 4542.5,3652.31 r0 top
H3 "DR52X62" DR52X62 251.17,380.65 r90 top
H4 "DR52X62" DR52X62 4542.5,380.65 r90 top
J1 "DC-JACK$2F$3P$2F$DIP$2F$R$2F$JD003-PF" DC-JACK$2F$3P$2F$DIP$2F$R$2F$JD003-PF 3942,512 r0 top
J2 "DIP4$2F$P2.54" DIP4$2F$P2.54 459,1264 r270 top
J13 "DIP7X2$2F$P2.54" DIP7X2$2F$P2.54 1089,3209 r0 top
J44 "CON10P$2F$SMD$2F$R$2F$F$2F$7SDCN-B0-1X14" CON10P$2F$SMD$2F$R$2F$F$2F$7SDCN-B0-1X14 1649,2841 r0 bottom
JP1 "DIP5X2$2F$P2.54" DIP5X2$2F$P2.54 209,3054 r0 bottom
JP2 "DIP5X2$2F$P2.54" DIP5X2$2F$P2.54 226,1604 r0 bottom
L4 "L$2F$IND$2F$SMD$2F$LVS5045" L$2F$IND$2F$SMD$2F$LVS5045 3010,2130 r0 bottom
L5 "L0402" L0402 2327.5,2400.5 r225 top
L6 "L0402" L0402 2408,2636 r135 top
L7 "L0402" L0402 2533,2729 r45 top
L8 "L0402" L0402 2482.25,2632.46 r45 top
L9 "L0402" L0402 2165.5,2641.5 r0 top
L10 "L0402" L0402 2161,2775.5 r0 top
L11 "L0402" L0402 2111.5,2691.5 r90 top
L12 "L0402" L0402 2063.5,2425.5 r270 top
L13 "L0402" L0402 2010.5,2407.5 r0 top
L14 "L0402" L0402 2437.5,2489.5 r225 top
L18 "L0201" L0201 3700,3024 r270 top
L19 "L0201" L0201 3842,3022 r180 top
L35 "L$2F$IND$2F$DIP$2F$D6H14" L$2F$IND$2F$DIP$2F$D6H14 4149,874 r180 top
L36 "L$2F$IND$2F$DIP$2F$D6H14" L$2F$IND$2F$DIP$2F$D6H14 4474,759 r90 top
L600 "L0402" L0402 2367,3163 r270 top
L601 "L0402" L0402 2919,2847 r180 top
L623 "L0402" L0402 2316.5,2511.64 r45 top
L624 "L0402" L0402 2338.82,2486.89 r45 top
L625 "L0402" L0402 2147.5,2489.5 r90 top
L626 "L0402" L0402 2111.5,2489.5 r90 top
L638 "L0402" L0402 1963,2642 r0 bottom
L639 "L0402" L0402 2044,2777.5 r0 bottom
L640 "L0402" L0402 2409,2734 r270 bottom
L641 "L0402" L0402 2269,2619 r0 bottom
L642 "L$2F$IND$2F$SMD$2F$LVS5045" L$2F$IND$2F$SMD$2F$LVS5045 4047,1825 r90 bottom
L643 "L$2F$IND$2F$SMD$2F$LVS5045" L$2F$IND$2F$SMD$2F$LVS5045 3665,1850 r90 top
L644 "L0603" L0603 3905,1930 r90 top
L645 "L0603" L0603 3975,2135 r90 top
L646 "L$2F$IND$2F$SMD$2F$LVS5045" L$2F$IND$2F$SMD$2F$LVS5045 3983,1155 r0 top
L647 "L0603" L0603 4187,1152 r0 top
L648 "L0603" L0603 4165,1440 r180 top
LA5 "L0402" L0402 3336,3396 r90 top
LA10 "L0402" L0402 4496,3292 r90 top
LA11 "L0402" L0402 3892,3072 r0 top
LA12 "L0402" L0402 3730,3068 r0 top
LA13 "L0402" L0402 3585,3396 r90 top
LA14 "L0402" L0402 4356,3292 r90 top
LA16 "L$2F$IND$2F$SMD$2F$VLS252012E" L$2F$IND$2F$SMD$2F$VLS252012E 4053,2579 r270 top
Q1 "LNA$2F$SOT-343$2F$SMD$2F$BF776" LNA$2F$SOT-343$2F$SMD$2F$BF776 2017.5,2707 r270 bottom
Q2 "LNA$2F$SOT-343$2F$SMD$2F$BF776" LNA$2F$SOT-343$2F$SMD$2F$BF776 2323,2680 r270 bottom
R21 "R0402" R0402 2840,2205 r180 bottom
R22 "R0402" R0402 2770,2245 r180 bottom
R23 "R0402" R0402 2336,2324 r45 bottom
R24 "R0402" R0402 2770,2205 r180 bottom
R26 "R0402" R0402 2595,2160 r180 top
R27 "R0402" R0402 2648.5,2177 r270 bottom
R28 "R0402" R0402 2715,2070 r180 top
R29 "R0402" R0402 2086,1690 r45 bottom
R42 "R0402" R0402 2201,1796 r90 bottom
R51 "R0402" R0402 2475,2150 r90 bottom
R52 "R0402" R0402 231,2551 r90 bottom
R53 "R0402" R0402 231,2633 r270 bottom
R54 "R0402" R0402 554,1164 r0 bottom
R55 "R0402" R0402 2254.8,1992.2 r225 bottom
R64 "R0402" R0402 1744.94,2069.07 r45 top
R65 "R0402" R0402 1496.5,1997.5 r180 bottom
R66 "R0402" R0402 1734.33,1973.61 r45 top
R67 "R0402" R0402 1654.5,1717.5 r180 bottom
R68 "R0402" R0402 1677.76,2030.18 r45 top
R69 "R0402" R0402 1566.5,1977.5 r180 bottom
R70 "R0402" R0402 1762.61,1945.33 r45 top
R71 "R0402" R0402 1720.5,1619.5 r180 bottom
R72 "R0402" R0402 1801.5,2012.5 r45 top
R73 "R0402" R0402 1496.5,1957.5 r180 bottom
R74 "R0402" R0402 1716.65,2097.35 r45 top
R75 "R0402" R0402 1655.5,1643.5 r180 bottom
R76 "R0402" R0402 1773.22,2040.78 r45 top
R77 "R0402" R0402 1566.5,1937.5 r180 bottom
R78 "R0402" R0402 1706.04,2001.89 r45 top
R79 "R0402" R0402 1723.5,1580.5 r180 bottom
R80 "R0402" R0402 1841.5,2267.5 r0 top
R81 "R0402" R0402 1496.5,1917.5 r180 bottom
R82 "R0402" R0402 1766.5,2367.5 r0 top
R83 "R0402" R0402 1655.5,1681.5 r180 bottom
R84 "R0402" R0402 1841.5,2307.5 r0 top
R85 "R0402" R0402 1721.5,1699.5 r180 bottom
R86 "R0402" R0402 1766.5,2327.5 r0 top
R87 "R0402" R0402 1496.5,1876.5 r180 bottom
R88 "R0402" R0402 1841.5,2347.5 r0 top
R89 "R0402" R0402 1722.5,1662.5 r180 bottom
R90 "R0402" R0402 1766.5,2287.5 r0 top
R91 "R0402" R0402 1841.5,2387.5 r0 top
R92 "R0402" R0402 1766.5,2247.5 r0 top
R93 "R0402" R0402 1829.79,1984.22 r225 top
R94 "R0402" R0402 1841.5,2227.5 r180 top
R95 "R0402" R0402 1790.9,1917.04 r225 top
R96 "R0402" R0402 1766.5,2207.5 r180 top
R97 "R0402" R0402 1723.5,1733.5 r180 bottom
R98 "R0402" R0402 1656.5,1772.5 r180 bottom
R99 "R0402" R0402 1631.89,2176.59 r180 top
R100 "R0402" R0402 1631.89,2141.24 r180 top
R101 "R0402" R0402 1725.5,1792.5 r180 bottom
R103 "R0402" R0402 1565.5,2075.5 r180 bottom
R104 "R0402" R0402 1566.5,2017.5 r180 bottom
R105 "R0402" R0402 1658.5,1812.5 r180 bottom
R106 "R0402" R0402 1498.5,2049.5 r180 bottom
R107 "R0402" R0402 2588,2532 r0 top
R108 "R0402" R0402 2679,2483 r0 top
R109 "R0402" R0402 2364,809 r90 top
R110 "R0402" R0402 2751,733 r90 top
R111 "R0402" R0402 2549,733 r90 top
R112 "R0402" R0402 1864,809 r90 top
R113 "R0402" R0402 2199,735 r90 top
R114 "R0402" R0402 2001,735 r90 top
R115 "R0402" R0402 1359,809 r90 top
R116 "R0402" R0402 1651,731 r90 top
R117 "R0402" R0402 1449,733 r90 top
R118 "R0402" R0402 854,809 r90 top
R119 "R0402" R0402 1101,735 r90 top
R120 "R0402" R0402 881,743 r90 top
R121 "R0402" R0402 3065,805 r90 top
R122 "R0402" R0402 3201,737 r90 top
R123 "R0402" R0402 3354,739 r90 top
R124 "R0402" R0402 2535,2236 r180 bottom
R125 "R0402" R0402 3014,3470 r270 top
R126 "R0402" R0402 2535,2202 r180 bottom
R127 "R0402" R0402 3048,3470 r270 top
R128 "R0402" R0402 1864,2544 r270 bottom
R129 "R0402" R0402 1804,2544 r270 bottom
R130 "R0402" R0402 1834,2544 r270 bottom
R131 "R0402" R0402 1769,2544 r270 bottom
R132 "R0402" R0402 2999,3692 r180 top
R133 "R0402" R0402 3134,3470 r270 top
R134 "R0402" R0402 2999,3659 r180 top
R135 "R0402" R0402 3100,3470 r270 top
R136 "R0402" R0402 1048,3558 r90 top
R137 "R0402" R0402 549,1089 r180 bottom
R139 "R0402" R0402 549,1054 r180 bottom
R142 "R0402" R0402 3453,3556 r270 top
R150 "R0402" R0402 1578.86,2157.5 r270 top
R151 "R0402" R0402 2980,3470 r90 top
R154 "R0402" R0402 380,1970 r90 top
R155 "R0402" R0402 2880,3560 r270 top
R156 "R0402" R0402 3470,3698 r180 top
R158 "R0402" R0402 674,3559 r270 top
R159 "R0402" R0402 733,3559 r90 top
R160 "R0402" R0402 2564,3562 r270 top
R161 "R0402" R0402 3504,3102 r0 top
R162 "R0402" R0402 3658,3146 r90 top
R163 "R0402" R0402 2249,3561 r270 top
R164 "R0402" R0402 3964,3170 r90 top
R165 "R0402" R0402 1933,3560 r270 top
R166 "R0402" R0402 1618,3554 r270 top
R167 "R0402" R0402 1297,3556 r270 top
R170 "R0402" R0402 2936,3028 r270 top
R172 "R0402" R0402 3522,3154 r270 top
R173 "R0402" R0402 3504,3204 r0 top
R174 "R0402" R0402 3814,3120 r0 top
R175 "R0402" R0402 3832,3170 r270 top
R176 "R0402" R0402 3814,3220 r0 top
R255 "SB$2F$1206" SB$2F$1206 4144,969 r180 top
R257 "SB$2F$1206" SB$2F$1206 4574,759 r90 top
R350 "R0402" R0402 926.5,2117.5 r270 top
R351 "R0402" R0402 1001.5,2117.5 r90 top
R355 "R0402" R0402 365,1220 r90 top
R370 "R0402" R0402 3474,3624 r180 top
R371 "R0402" R0402 1670,2774 r180 bottom
R372 "R0402" R0402 3188,3559 r270 top
R373 "R0402" R0402 1570,2773 r180 bottom
R374 "R0402" R0402 989,3560 r270 top
R375 "R0402" R0402 879,2769 r0 bottom
R376 "R0402" R0402 974,2769 r180 bottom
R377 "R0402" R0402 1469,2772 r180 bottom
R381 "R0402" R0402 2454,2199 r0 bottom
R382 "R0402" R0402 2675,2230 r0 top
R383 "R0402" R0402 2675,2265 r0 top
R388 "R0402" R0402 780,2775 r0 bottom
R389 "R0402" R0402 679,3758.5 r0 bottom
R471 "R0402" R0402 1709,3124 r180 top
R472 "R0402" R0402 1569,3139 r0 top
R473 "R0402" R0402 1499,3139 r180 top
R474 "R0402" R0402 1389,3104 r90 top
R475 "R0402" R0402 1289,3104 r90 top
R476 "R0402" R0402 1189,3104 r90 top
R477 "R0402" R0402 1107,3130 r180 top
R478 "R0402" R0402 1254,3104 r270 top
R479 "R0402" R0402 1498.5,2086.5 r180 bottom
R810 "R0402" R0402 3113.5,2501 r90 top
R812 "R0402" R0402 1744,2272 r270 bottom
R813 "R0402" R0402 1901.5,2235.5 r270 bottom
R814 "R0402" R0402 2660,1985 r180 top
R815 "R0402" R0402 2660,2015 r180 top
R823 "R0402" R0402 3556,3538 r0 top
R824 "R0402" R0402 3489,3556 r90 top
R825 "R0402" R0402 3626,3538 r0 top
R826 "R0402" R0402 1567.5,1899.5 r180 bottom
R827 "R0402" R0402 1654.5,1601.5 r180 bottom
R829 "C0402" C0402 3180,1670 r270 bottom
R830 "R0603" R0603 3180,1760 r90 bottom
R868 "R0402" R0402 3677,3408 r180 top
R869 "R0402" R0402 4152,3310 r180 top
R894 "R0402" R0402 970,2915 r0 top
R895 "R0603" R0603 4535,1970 r90 top
R896 "R0402" R0402 283,2465 r180 bottom
R897 "R0402" R0402 333,2288 r180 bottom
R898 "R0402" R0402 1040,2915 r0 top
R899 "R0402" R0402 334,2220 r0 bottom
R900 "R0805" R0805 874,2464 r270 top
R902 "R0402" R0402 444,1434 r180 bottom
R903 "R0402" R0402 344,1675 r180 top
R904 "R0402" R0402 344,1433 r180 top
R906 "R0402" R0402 243,1433 r180 bottom
R907 "R0402" R0402 578,1421 r0 bottom
R908 "R0402" R0402 595,1369 r90 bottom
R909 "R0402" R0402 636,1404 r90 bottom
R910 "R0402" R0402 244,1679 r180 bottom
R911 "R0402" R0402 560,1369 r90 bottom
R912 "R0402" R0402 1791,2609 r180 bottom
R913 "R0402" R0402 1859,2641 r180 bottom
R914 "R0402" R0402 1991,2793.5 r270 bottom
R918 "R0402" R0402 1973,2847 r180 bottom
R919 "R0402" R0402 2369.5,2897.5 r90 top
R921 "R0402" R0402 2758,2826 r90 top
R922 "R0402" R0402 2354.5,2785 r0 bottom
R923 "R0402" R0402 2179.5,2498.5 r270 bottom
R924 "R0402" R0402 2181.5,2601.5 r270 bottom
R928 "R0402" R0402 2285,2817 r180 bottom
R932 "R0402" R0402 1780,2570 r90 top
R940 "R0402" R0402 4575.5,1604.5 r180 bottom
R941 "R0402" R0402 4574,1765 r180 bottom
R942 "R0402" R0402 3216.5,1713 r0 top
R943 "R0402" R0402 4630,1672 r270 bottom
R944 "R0402" R0402 3440,1875 r180 top
R945 "R0402" R0402 4574,1730 r0 bottom
R946 "R0402" R0402 3218,1821 r0 top
R947 "R0402" R0402 3365,1875 r180 top
R948 "R0402" R0402 3662,1522 r270 top
R949 "R0402" R0402 3843,1495 r180 top
R950 "R0402" R0402 3733,1571 r180 top
R951 "R0402" R0402 3788,1515 r90 top
R952 "R0402" R0402 1929,2402 r135 bottom
R953 "R0402" R0402 1904,2381 r135 bottom
R954 "R0402" R0402 1804,2764 r270 top
RA7 "R0402" R0402 3460.69,2648.48 r180 top
RA9 "R0402" R0402 3400,2530 r270 top
RA10 "R0402" R0402 4044.88,2812 r180 top
RA11 "R0402" R0402 3803,2526 r270 bottom
RA12 "R0402" R0402 3855,2486 r270 bottom
RA13 "R0402" R0402 3400,2598 r270 top
RA15 "R0402" R0402 3670.36,2499.58 r90 top
RA18 "R0402" R0402 3535,2510 r180 top
RA19 "R0402" R0402 3763,2378 r270 bottom
RA20 "R0402" R0402 3587,2774 r0 bottom
RA21 "R0402" R0402 4214,2678 r0 top
RC1 "C0603" C0603 265,2252 r270 bottom
S2 "SW$2F$4P$2F$DIP$2F$TS02-CN-PF" SW$2F$4P$2F$DIP$2F$TS02-CN-PF 185,1905 r270 top
S3 "SW$2F$4P$2F$DIP$2F$TS02-CN-PF" SW$2F$4P$2F$DIP$2F$TS02-CN-PF 180,1170 r270 top
SHA1 "SHIELDING$2F$MPCIE$2F$2H$2F$T2" SHIELDING$2F$MPCIE$2F$2H$2F$T2 3810.5,2748.5 r0 top
SR1 "R0402" R0402 2585,2330 r0 bottom
SR2 "R0402" R0402 3036,3028 r90 top
TP246 "TP30MIL" TP30MIL 4122,2856 r0 top
TP249 "TP30MIL" TP30MIL 4220,2735 r0 top
TP250 "TP30MIL" TP30MIL 3980,2745 r180 bottom
TP251 "TP30MIL" TP30MIL 3980,2790 r180 bottom
TP601 "PAD$2F$1P$2F$0.5MM" PAD$2F$1P$2F$0.5MM 2389,2174 r180 bottom
TP605 "PAD$2F$1P$2F$0.5MM" PAD$2F$1P$2F$0.5MM 2185,2220 r180 bottom
U1 "MT7620AE2$2F$TFBGA265$2F$P0.65$2F$B0.3$2F$11X11" MT7620AE2$2F$TFBGA265$2F$P0.65$2F$B0.3$2F$11X11 2222.5,2091.5 r315 top
U6 "SOT-23-6$2F$SMD$2F$P0.95$2F$APM2701AC" SOT-23-6$2F$SMD$2F$P0.95$2F$APM2701AC 2811,2120 r90 bottom
U8 "SOT89$2F$SMD" SOT89$2F$SMD 3025,1760 r0 bottom
U9 "SOIC8$2F$SMD$2F$P1.27$2F$AT24C04B-08B" SOIC8$2F$SMD$2F$P1.27$2F$AT24C04B-08B 383,2640 r270 bottom
U11 "CRYS$2F$SMD$2F$D3.2X2.5$2F$E3SB40$2F$HOSONIC" CRYS$2F$SMD$2F$D3.2X2.5$2F$E3SB40$2F$HOSONIC 2995,2510 r0 top
U12 "TRANSFORMER$2F$20P$2F$DIP$2F$HN2066CG" TRANSFORMER$2F$20P$2F$DIP$2F$HN2066CG 2114,1049 r180 top
U13 "RJ45$2F$32P$2F$DIP$2F$R$2F$N3642-001" RJ45$2F$32P$2F$DIP$2F$R$2F$N3642-001 751,541 r0 top
U14 "TRANSFORMER$2F$20P$2F$DIP$2F$HN2066CG" TRANSFORMER$2F$20P$2F$DIP$2F$HN2066CG 1109,1049 r180 top
U15 "RJ45$2F$8P$2F$DIP$2F$R$2F$N3612-002" RJ45$2F$8P$2F$DIP$2F$R$2F$N3612-002 3051,541 r0 top
U16 "TRANSFORMER$2F$16P$2F$DIP$2F$HN1674CG" TRANSFORMER$2F$16P$2F$DIP$2F$HN1674CG 3019,1044 r180 top
U18 "SOIC8$2F$SMD$2F$P1.27$2F$AT26DF321" SOIC8$2F$SMD$2F$P1.27$2F$AT26DF321 3012,3246 r0 top
U21 "SKY85601" SKY85601 3624,3263 r270 top
U22 "WBGA84$2F$SMD$2F$P0.8$2F$W9751G6IB" WBGA84$2F$SMD$2F$P0.8$2F$W9751G6IB 1240.05,2150.82 r270 top
U33 "CRYS$2F$DIP$2F$D5X10.6$2F$GB2000025$2F$ECERA" CRYS$2F$DIP$2F$D5X10.6$2F$GB2000025$2F$ECERA 2991,2509 r90 top
U626 "SOT223-3$2F$SMD$2F$P2.3$2F$AX1007" SOT223-3$2F$SMD$2F$P2.3$2F$AX1007 929,2724 r180 top
U627 "SOT-143$2F$SMD$2F$G693" SOT-143$2F$SMD$2F$G693 304,2381 r180 bottom
U630 "TSON6$2F$SMD$2F$P0.65$2F$UPG2179TB" TSON6$2F$SMD$2F$P0.65$2F$UPG2179TB 2219,2948.5 r270 top
U631 "TSON6$2F$SMD$2F$P0.65$2F$UPG2179TB" TSON6$2F$SMD$2F$P0.65$2F$UPG2179TB 2606,2880.5 r270 top
U632 "SOT-353" SOT-353 1779,2664 r0 top
U634 "SOP8$2F$SMD$2F$P1.27$2F$IT7653" SOP8$2F$SMD$2F$P1.27$2F$IT7653 4354,1656 r90 bottom
U635 "SOP8$2F$SMD$2F$P1.27$2F$IT7653" SOP8$2F$SMD$2F$P1.27$2F$IT7653 3405,1750 r90 top
U636 "SOP8$2F$SMD$2F$P1.27$2F$IT7653" SOP8$2F$SMD$2F$P1.27$2F$IT7653 3710,1309 r0 top
U637 "BPF20125$2F$MURATA-KIM" BPF20125$2F$MURATA-KIM 3677,3408 r180 top
U638 "BPF20125$2F$MURATA-KIM" BPF20125$2F$MURATA-KIM 4152,3310 r180 top
U639 "SKY85601" SKY85601 3934,3282 r270 top
UA4 "MT7662$2F$WSQFN76$2F$SMD$2F$P0.4$2F$9X9$2F$S" MT7662$2F$WSQFN76$2F$SMD$2F$P0.4$2F$9X9$2F$S 3799,2774 r270 top
UA5 "CRYS$2F$SMD$2F$D3.2X2.5$2F$E3SB40$2F$HOSONIC" CRYS$2F$SMD$2F$D3.2X2.5$2F$E3SB40$2F$HOSONIC 3467,2790 r0 top
UC1 "C0402" C0402 3976,3481 r180 bottom
UC2 "C0402" C0402 4046,3481 r0 bottom
USB1 "USB$2F$4P$2F$DIP$2F$ATOM$2F$A" USB$2F$4P$2F$DIP$2F$ATOM$2F$A 4008.77,3545.58 r180 top

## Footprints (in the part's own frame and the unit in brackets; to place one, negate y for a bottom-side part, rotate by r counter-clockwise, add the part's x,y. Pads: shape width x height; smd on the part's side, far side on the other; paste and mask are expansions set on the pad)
BPF20125$2F$MURATA-KIM [mm]
  rect 1.65x0.75 smd: 1(0,0.85) 3(0,-0.85)
  rect 0.95x0.35 smd: 2(1.225,0) 4(-1.225,0)
  silkscreen extent -1.3,-0.67 1.05,0.92
C100UF25V$2F$D6.3H11.5 [mm]
  rect 1.3x1.3 / inner round 1.3 / far side rect 1.3x1.3 hole 0.8: 1(-1.25,0)
  round 1.3 hole 0.8: 2(1.25,0)
  silkscreen extent -3.45,-3.45 3.45,3.81
C0201 [mil]
  rect 12x12 smd: 1(-10,0) 2(10,0)
  silkscreen extent -20,-10 20,10
C0402 [mil]
  rect 20x20 smd: 1(-18,0) 2(18,0)
  silkscreen extent -33,-15 33,15
C0402A [mil]
  rect 20x20 smd: 1(-18,0) 2(18,0)
  silkscreen extent -33,-15 33,15
C0603 [mil]
  rect 28x32 smd: 1(-25.59,0) 2(25.59,0)
  silkscreen extent -48,-25 48,25
C680UF6.3V$2F$D8H11 [mm]
  rect 1.3x1.3 / inner round 1.3 / far side rect 1.3x1.3 hole 0.8: 1(-1.75,0)
  round 1.3 hole 0.8: 2(1.75,0)
  silkscreen extent -4.1,-4.1 4.1,4.25
C0805 [mil]
  rect 34x56 smd: 1(-34.45,0) 2(34.45,0)
  silkscreen extent -63,-38 63,38
C1206 [mm]
  rect 1x1.8 smd: 1(-1.4,0) 2(1.4,0)
  silkscreen extent -2.2,-1.2 2.2,1.2
COAXIAL$2F$SMD$2F$CON$2F$V$2F$I-PEX [mm]
  rect 1x1.05 smd: 1(0,-1.525)
  rect 1.05x2.2 smd: 2(-1.475,0) 3(1.475,0)
  silkscreen extent -1.63,-1.63 1.63,1.63
COAXIAL$2F$SMD$2F$CON$2F$V$2F$I-PEX$2F$W08-5801 [mm]
  rect 1x1.05 smd: 1(0,-1.525)
  rect 1.05x2.2 smd: 2(-1.475,0) 3(1.475,0)
  silkscreen extent -1.6,-1.6 1.6,1.6
CON10P$2F$SMD$2F$R$2F$F$2F$7SDCN-B0-1X14 [mm]
  rect 1.1x2 smd: 1(-2.5,0) 2(-5,0) 3(-7.5,0) 4(-10,0) 5(-12.5,0) 6(-15,0) 7(-17.4,0) 8(-19.1,0) 9(0,0) CD(-21.6,0)
  rect 1.5x1.5 smd: GND1(-22.5,-12) GND2(5.4,-24.5) WP(-22.5,-23.5)
  round 1.7 hole 1.2 unplated: H1(-18.55,-3.5) H2(1.45,-3.5)
  silkscreen extent -22.95,-25.6 5.65,0.1
CRYS$2F$DIP$2F$D5X10.6$2F$GB2000025$2F$ECERA [mm]
  round 1.23 hole 0.73: 1(-2.44,0) 2(2.44,0)
  silkscreen extent -5.79,-2.62 5.79,2.62
CRYS$2F$SMD$2F$D3.2X2.5$2F$E3SB40$2F$HOSONIC [mm]
  rect 1.4x1.2 smd: 1(-1.1,-0.8) 2(1.1,-0.8) 3(1.1,0.8) 4(-1.1,0.8)
  silkscreen extent -2,-1.6 1.7,1.35
DC-JACK$2F$3P$2F$DIP$2F$R$2F$JD003-PF [mm]
  oval 3.1x1.1 hole 0.6 slot 2.6 at 0 deg: 1(0,-6)
  oval 1.1x2.9 hole 0.6 slot 2.4 at 90 deg: 2(4.8,-2.8)
  oval 3.6x1.1 hole 0.6 slot 3.1 at 0 deg: 3(0,0)
  silkscreen extent -4.6,-13.9 4.6,0.8
DIP4$2F$P2.54 [mil]
  rect 58x58 hole 39: 1(0,0)
  round 58 hole 39: 2(100,0) 3(200,0) 4(300,0)
  silkscreen extent -60,-50 350,60
DIP5X2$2F$P2.54 [mil]
  rect 58x58 hole 39: 1(0,0)
  round 58 hole 39: 2(0,100) 3(100,0) 4(100,100) 5(200,0) 6(200,100) 7(300,0) 8(300,100) 9(400,0) 10(400,100)
  silkscreen extent -50,-50 450,150
DIP7X2$2F$P2.54 [mil]
  rect 58x58 hole 39: 1(0,0)
  round 58 hole 39: 2(0,100) 3(100,0) 4(100,100) 5(200,0) 6(200,100) 7(300,0) 8(300,100) 9(400,0) 10(400,100) 11(500,0) 12(500,100) 13(600,0) 14(600,100)
  silkscreen extent -50,-60 650,160
DR52 [mil]
  round 205 hole 205 unplated: 1(0,0)
DR52X62 [mil]
  oval 245x205 hole 205 slot 245 at 0 deg unplated: 1(0,0)
FD [mm]
  round 1 smd: 1(0,0)
  Top keep-out region: 1.168,0 1.079,0.447 0.826,0.826 0.447,1.079 0,1.168 0,1.168 -0.447,1.079 -0.826,0.826 -1.079,0.447 -1.168,0 -1.168,0 -1.079,-0.447 -0.826,-0.826 -0.447,-1.079 0,-1.168 0,-1.168 0.447,-1.079 0.826,-0.826 1.079,-0.447 1.168,0
L0201 [mil]
  rect 12x12 smd: 1(-10,0) 2(10,0)
  silkscreen extent -20,-10 20,10
L0402 [mil]
  rect 20x20 smd: 1(-18,0) 2(18,0)
  silkscreen extent -33,-15 33,15
L0603 [mil]
  rect 28x32 smd: 1(-25.59,0) 2(25.59,0)
  silkscreen extent -48,-25 48,25
L$2F$IND$2F$DIP$2F$D6H14 [mil]
  round 55 hole 35: 1(-59.06,0) 2(59.06,0)
  silkscreen extent -118,-123 121,123
L$2F$IND$2F$SMD$2F$LVS5045 [mm]
  rect 2.1x5 smd: 1(-1.6,0) 2(1.6,0)
  Top keep-out region: -0.556,2.507 0.551,2.507 0.551,-2.504 -0.556,-2.504 -0.556,2.507
  silkscreen extent -2.6,-2.6 2.6,2.6
L$2F$IND$2F$SMD$2F$VLS252012E [mm]
  rect 0.85x2 smd: 1(-0.825,0) 2(0.825,0)
  silkscreen extent -1.35,-1.1 1.35,1.1
LNA$2F$SOT-343$2F$SMD$2F$BF776 [mm]
  rect 0.6x0.8 smd: 1(-0.65,-0.8) 3(0.65,0.8) 4(-0.65,0.8)
  rect 0.9x0.8 smd: 2(0.5,-0.8)
  silkscreen extent -1.32,-1.38 1.05,0.67
MT7620AE2$2F$TFBGA265$2F$P0.65$2F$B0.3$2F$11X11 [mm]
  round 0.3 smd: A1(-5.2,5.2) A2(-4.55,5.2) A3(-3.9,5.2) A4(-3.25,5.2) A5(-2.6,5.2) A6(-1.95,5.2) A7(-1.3,5.2) A8(-0.65,5.2) A9(0,5.2) A10(0.65,5.2) A11(1.3,5.2) A13(2.6,5.2) A14(3.25,5.2) A15(3.9,5.2) A16(4.55,5.2) A17(5.2,5.2) B1(-5.2,4.55) B2(-4.55,4.55) B3(-3.9,4.55) B4(-3.25,4.55) B5(-2.6,4.55) B7(-1.3,4.55) B8(-0.65,4.55) B9(0,4.55) B10(0.65,4.55) B11(1.3,4.55) B14(3.25,4.55) B15(3.9,4.55) B16(4.55,4.55) B17(5.2,4.55) C1(-5.2,3.9) C2(-4.55,3.9) C4(-3.25,3.9) C5(-2.6,3.9) C6(-1.95,3.9) C7(-1.3,3.9) C8(-0.65,3.9) C9(0,3.9) C10(0.65,3.9) C11(1.3,3.9) C12(1.95,3.9) C14(3.25,3.9) C15(3.9,3.9) C16(4.55,3.9) C17(5.2,3.9) D1(-5.2,3.25) D2(-4.55,3.25) D3(-3.9,3.25) D4(-3.25,3.25) D5(-2.6,3.25) D6(-1.95,3.25) D7(-1.3,3.25) D8(-0.65,3.25) D9(0,3.25) D10(0.65,3.25) D11(1.3,3.25) D12(1.95,3.25) D14(3.25,3.25) D15(3.9,3.25) D16(4.55,3.25) D17(5.2,3.25) E1(-5.2,2.6) E2(-4.55,2.6) E3(-3.9,2.6) E4(-3.25,2.6) E5(-2.6,2.6) E6(-1.95,2.6) E7(-1.3,2.6) E8(-0.65,2.6) E9(0,2.6) E10(0.65,2.6) E13(2.6,2.6) E14(3.25,2.6) E15(3.9,2.6) E16(4.55,2.6) E17(5.2,2.6) F2(-4.55,1.95) F6(-1.95,1.95) F7(-1.3,1.95) F8(-0.65,1.95) F9(0,1.95) F10(0.65,1.95) F11(1.3,1.95) F12(1.95,1.95) F13(2.6,1.95) F14(3.25,1.95) F15(3.9,1.95) F16(4.55,1.95) F17(5.2,1.95) G4(-3.25,1.3) G5(-2.6,1.3) G6(-1.95,1.3) G7(-1.3,1.3) G8(-0.65,1.3) G9(0,1.3) G10(0.65,1.3) G11(1.3,1.3) G12(1.95,1.3) G13(2.6,1.3) G14(3.25,1.3) G15(3.9,1.3) G16(4.55,1.3) G17(5.2,1.3) H1(-5.2,0.65) H2(-4.55,0.65) H3(-3.9,0.65) H4(-3.25,0.65) H5(-2.6,0.65) H6(-1.95,0.65) H7(-1.3,0.65) H8(-0.65,0.65) H9(0,0.65) H10(0.65,0.65) H11(1.3,0.65) H12(1.95,0.65) H14(3.25,0.65) H15(3.9,0.65) H16(4.55,0.65) H17(5.2,0.65) J1(-5.2,0) J2(-4.55,0) J3(-3.9,0) J4(-3.25,0) J5(-2.6,0) J6(-1.95,0) J7(-1.3,0) J8(-0.65,0) J9(0,0) J10(0.65,0) J11(1.3,0) J12(1.95,0) J14(3.25,0) J15(3.9,0) J16(4.55,0) J17(5.2,0) K1(-5.2,-0.65) K2(-4.55,-0.65) K3(-3.9,-0.65) K4(-3.25,-0.65) K5(-2.6,-0.65) K6(-1.95,-0.65) K7(-1.3,-0.65) K8(-0.65,-0.65) K9(0,-0.65) K10(0.65,-0.65) K11(1.3,-0.65) K12(1.95,-0.65) K13(2.6,-0.65) K14(3.25,-0.65) K15(3.9,-0.65) L1(-5.2,-1.3) L2(-4.55,-1.3) L3(-3.9,-1.3) L4(-3.25,-1.3) L5(-2.6,-1.3) L6(-1.95,-1.3) L7(-1.3,-1.3) L8(-0.65,-1.3) L9(0,-1.3) L10(0.65,-1.3) L11(1.3,-1.3) L12(1.95,-1.3) L13(2.6,-1.3) L14(3.25,-1.3) L15(3.9,-1.3) M1(-5.2,-1.95) M2(-4.55,-1.95) M3(-3.9,-1.95) M4(-3.25,-1.95) M5(-2.6,-1.95) M6(-1.95,-1.95) M7(-1.3,-1.95) M8(-0.65,-1.95) M9(0,-1.95) M10(0.65,-1.95) M11(1.3,-1.95) M12(1.95,-1.95) M13(2.6,-1.95) M14(3.25,-1.95) M15(3.9,-1.95) M16(4.55,-1.95) M17(5.2,-1.95) N1(-5.2,-2.6) N2(-4.55,-2.6) N3(-3.9,-2.6) N4(-3.25,-2.6) N5(-2.6,-2.6) N6(-1.95,-2.6) N9(0,-2.6) N10(0.65,-2.6) N11(1.3,-2.6) N12(1.95,-2.6) N13(2.6,-2.6) N14(3.25,-2.6) N15(3.9,-2.6) N16(4.55,-2.6) N17(5.2,-2.6) P1(-5.2,-3.25) P2(-4.55,-3.25) P3(-3.9,-3.25) P4(-3.25,-3.25) P5(-2.6,-3.25) P6(-1.95,-3.25) P7(-1.3,-3.25) P8(-0.65,-3.25) P9(0,-3.25) P10(0.65,-3.25) P11(1.3,-3.25) P12(1.95,-3.25) P13(2.6,-3.25) P14(3.25,-3.25) P15(3.9,-3.25) P16(4.55,-3.25) P17(5.2,-3.25) R1(-5.2,-3.9) R2(-4.55,-3.9) R3(-3.9,-3.9) R4(-3.25,-3.9) R5(-2.6,-3.9) R6(-1.95,-3.9) R7(-1.3,-3.9) R8(-0.65,-3.9) R9(0,-3.9) R10(0.65,-3.9) R11(1.3,-3.9) R12(1.95,-3.9) R13(2.6,-3.9) R14(3.25,-3.9) R15(3.9,-3.9) R16(4.55,-3.9) R17(5.2,-3.9) T1(-5.2,-4.55) T2(-4.55,-4.55) T3(-3.9,-4.55) T4(-3.25,-4.55) T5(-2.6,-4.55) T6(-1.95,-4.55) T7(-1.3,-4.55) T8(-0.65,-4.55) T9(0,-4.55) T10(0.65,-4.55) T11(1.3,-4.55) T12(1.95,-4.55) T13(2.6,-4.55) T14(3.25,-4.55) T15(3.9,-4.55) T16(4.55,-4.55) T17(5.2,-4.55) U1(-5.2,-5.2) U2(-4.55,-5.2) U3(-3.9,-5.2) U4(-3.25,-5.2) U5(-2.6,-5.2) U6(-1.95,-5.2) U7(-1.3,-5.2) U8(-0.65,-5.2) U9(0,-5.2) U10(0.65,-5.2) U11(1.3,-5.2) U12(1.95,-5.2) U13(2.6,-5.2) U14(3.25,-5.2) U15(3.9,-5.2) U16(4.55,-5.2) U17(5.2,-5.2)
  silkscreen extent -6,-5.6 5.6,6
MT7662$2F$WSQFN76$2F$SMD$2F$P0.4$2F$9X9$2F$S [mm]
  rect 0.22x0.7 smd: 1(-3.6,-4.45) 2(-3.2,-4.45) 3(-2.8,-4.45) 4(-2.4,-4.45) 5(-2,-4.45) 6(-1.6,-4.45) 7(-1.2,-4.45) 8(-0.8,-4.45) 9(-0.4,-4.45) 10(0,-4.45) 11(0.4,-4.45) 12(0.8,-4.45) 13(1.2,-4.45) 14(1.6,-4.45) 15(2,-4.45) 16(2.4,-4.45) 17(2.8,-4.45) 18(3.2,-4.45) 19(3.6,-4.45) 39(3.6,4.45) 40(3.2,4.45) 41(2.8,4.45) 42(2.4,4.45) 43(2,4.45) 44(1.6,4.45) 45(1.2,4.45) 46(0.8,4.45) 47(0.4,4.45) 48(0,4.45) 49(-0.4,4.45) 50(-0.8,4.45) 51(-1.2,4.45) 52(-1.6,4.45) 53(-2,4.45) 54(-2.4,4.45) 55(-2.8,4.45) 56(-3.2,4.45) 57(-3.6,4.45)
  rect 0.7x0.22 smd: 20(4.45,-3.6) 21(4.45,-3.2) 22(4.45,-2.8) 23(4.45,-2.4) 24(4.45,-2) 25(4.45,-1.6) 26(4.45,-1.2) 27(4.45,-0.8) 28(4.45,-0.4) 29(4.45,0) 30(4.45,0.4) 31(4.45,0.8) 32(4.45,1.2) 33(4.45,1.6) 34(4.45,2) 35(4.45,2.4) 36(4.45,2.8) 37(4.45,3.2) 38(4.45,3.6) 58(-4.45,3.6) 59(-4.45,3.2) 60(-4.45,2.8) 61(-4.45,2.4) 62(-4.45,2) 63(-4.45,1.6) 64(-4.45,1.2) 65(-4.45,0.8) 66(-4.45,0.4) 67(-4.45,0) 68(-4.45,-0.4) 69(-4.45,-0.8) 70(-4.45,-1.2) 71(-4.45,-1.6) 72(-4.45,-2) 73(-4.45,-2.4) 74(-4.45,-2.8) 75(-4.45,-3.2) 76(-4.45,-3.6)
  rect 7.2x7.2 smd: 77(0,0)
  silkscreen extent -4.8,-4.8 4.55,4.55
PAD$2F$1P$2F$0.5MM [mil]
  round 20 smd: 1(-0.39,0.26)
  silkscreen extent -15,-15 15,15
R0402 [mil]
  rect 20x20 smd: 1(-18,0) 2(18,0)
  silkscreen extent -33,-15 33,15
R0603 [mil]
  rect 28x32 smd: 1(-25.59,0) 2(25.59,0)
  silkscreen extent -48,-25 48,25
R0805 [mil]
  rect 34x56 smd: 1(-34.45,0) 2(34.45,0)
  silkscreen extent -62,-38 63,38
RJ45$2F$8P$2F$DIP$2F$R$2F$N3612-002 [mm]
  rect 1.4x1.4 / inner round 1.4 / far side rect 1.4x1.4 hole 0.9: 1(0,0)
  round 1.4 hole 0.9: 2(1.27,2.54) 3(2.54,0) 4(3.81,2.54) 5(5.08,0) 6(6.35,2.54) 7(7.62,0) 8(8.89,2.54)
  round 3.2 hole 3.2 unplated: 9(-1.27,-6.35) 10(10.16,-6.35)
  silkscreen extent -3.25,-13.95 12.14,3.85
RJ45$2F$32P$2F$DIP$2F$R$2F$N3642-001 [mm]
  rect 1.4x1.4 / inner round 1.4 / far side round 1.4 hole 0.9: 1(0,0)
  round 1.4 hole 0.9: 2(1.27,2.54) 3(2.54,0) 4(3.81,2.54) 5(5.08,0) 6(6.35,2.54) 7(7.62,0) 8(8.89,2.54) 9(13.97,0) 10(15.24,2.54) 11(16.51,0) 12(17.78,2.54) 13(19.05,0) 14(20.32,2.54) 15(21.59,0) 16(22.86,2.54) 17(27.94,0) 18(29.21,2.54) 19(30.48,0) 20(31.75,2.54) 21(33.02,0) 22(34.29,2.54) 23(35.56,0) 24(36.83,2.54) 25(41.91,0) 26(43.18,2.54) 27(44.45,0) 28(45.72,2.54) 29(46.99,0) 30(48.26,2.54) 31(49.53,0) 32(50.8,2.54)
  round 3.2 hole 3.2 unplated: 33(-1.27,-6.35) 34(52.07,-6.35)
  silkscreen extent -3.9,-13.95 54.7,3.85
SB$2F$1206 [mm]
  rect 1x1.8 smd: 1(-1.4,0) 2(1.4,0)
  Top region: 0,-0.9 1.9,-0.9 1.9,0.9 0,0.9 0,-0.9
  Top region: -1.9,0.9 0,0.9 0,-0.9 -1.9,-0.9 -1.9,0.9
  silkscreen extent -2.2,-1.2 2.2,1.2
